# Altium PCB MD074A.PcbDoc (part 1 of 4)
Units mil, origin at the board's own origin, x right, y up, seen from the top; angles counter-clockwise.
Board outline 3224.41 x 4078.74 mil, 4 copper layers (Top Layer, Signal Layer 1, Signal Layer 2, Bottom Layer), stack 61.2 mil thick; 217 components, 121 nets, 624 pads, 901 vias.
Unrouted connection lines stored in the file: 116.
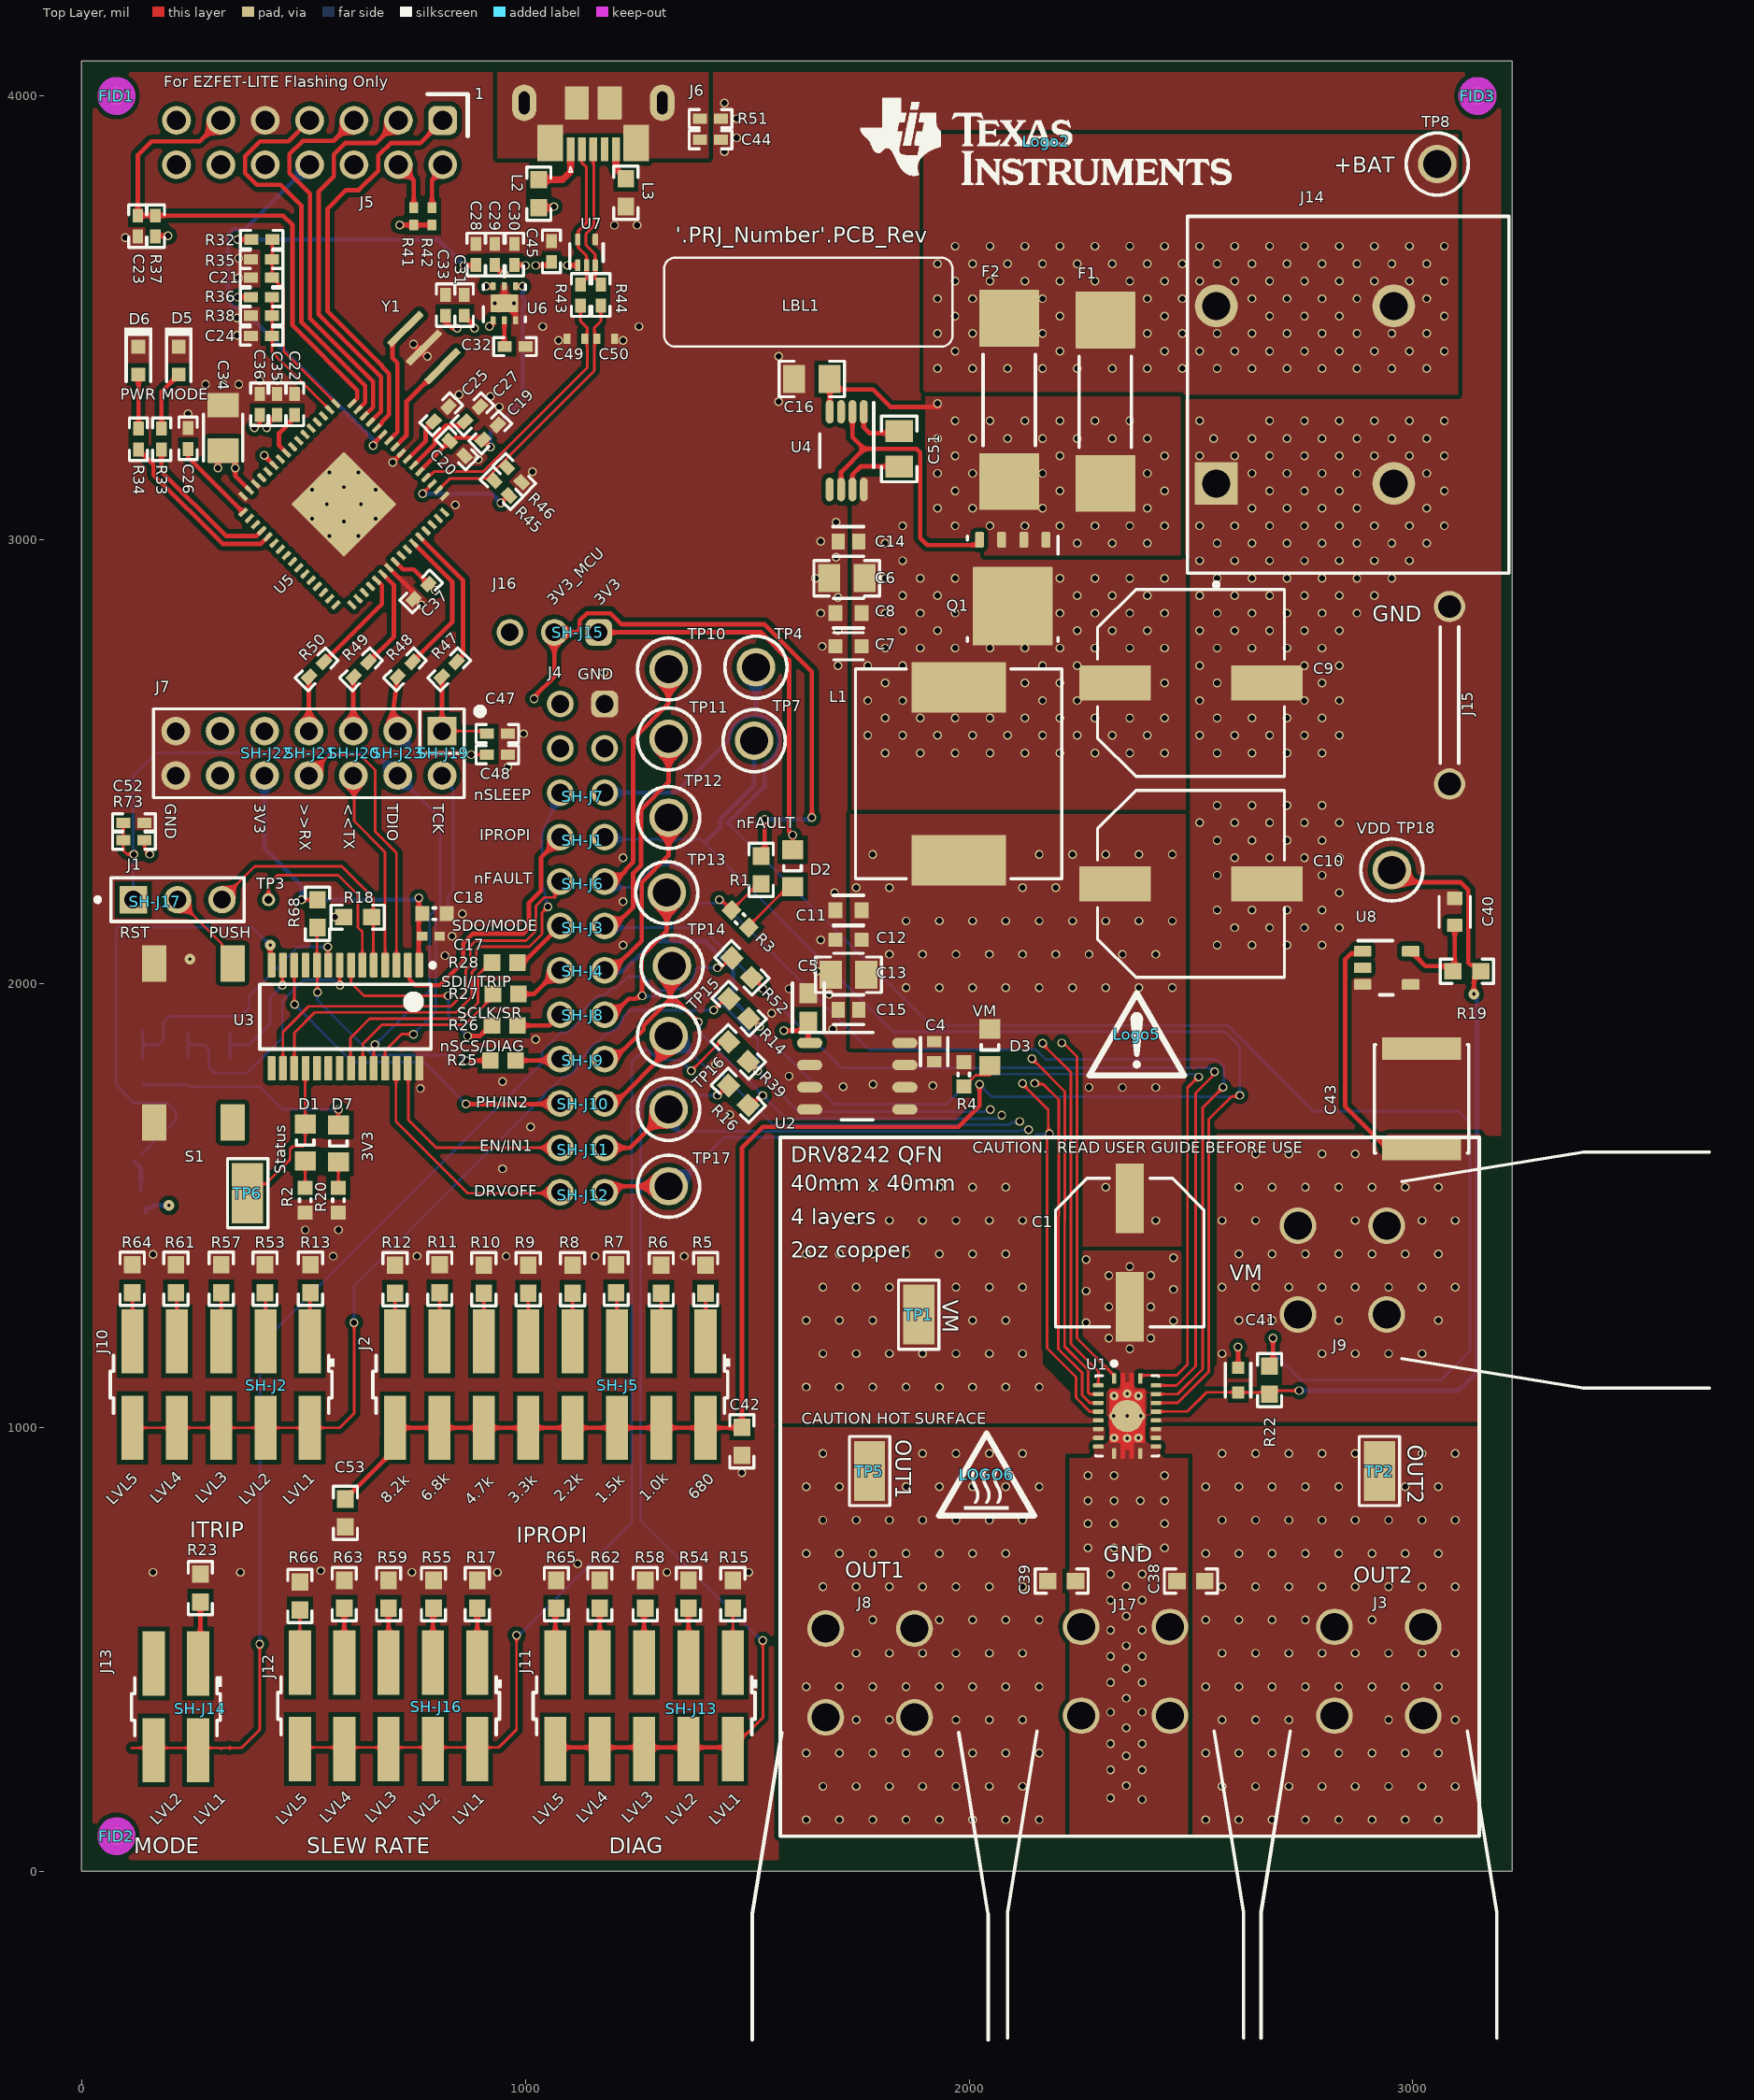
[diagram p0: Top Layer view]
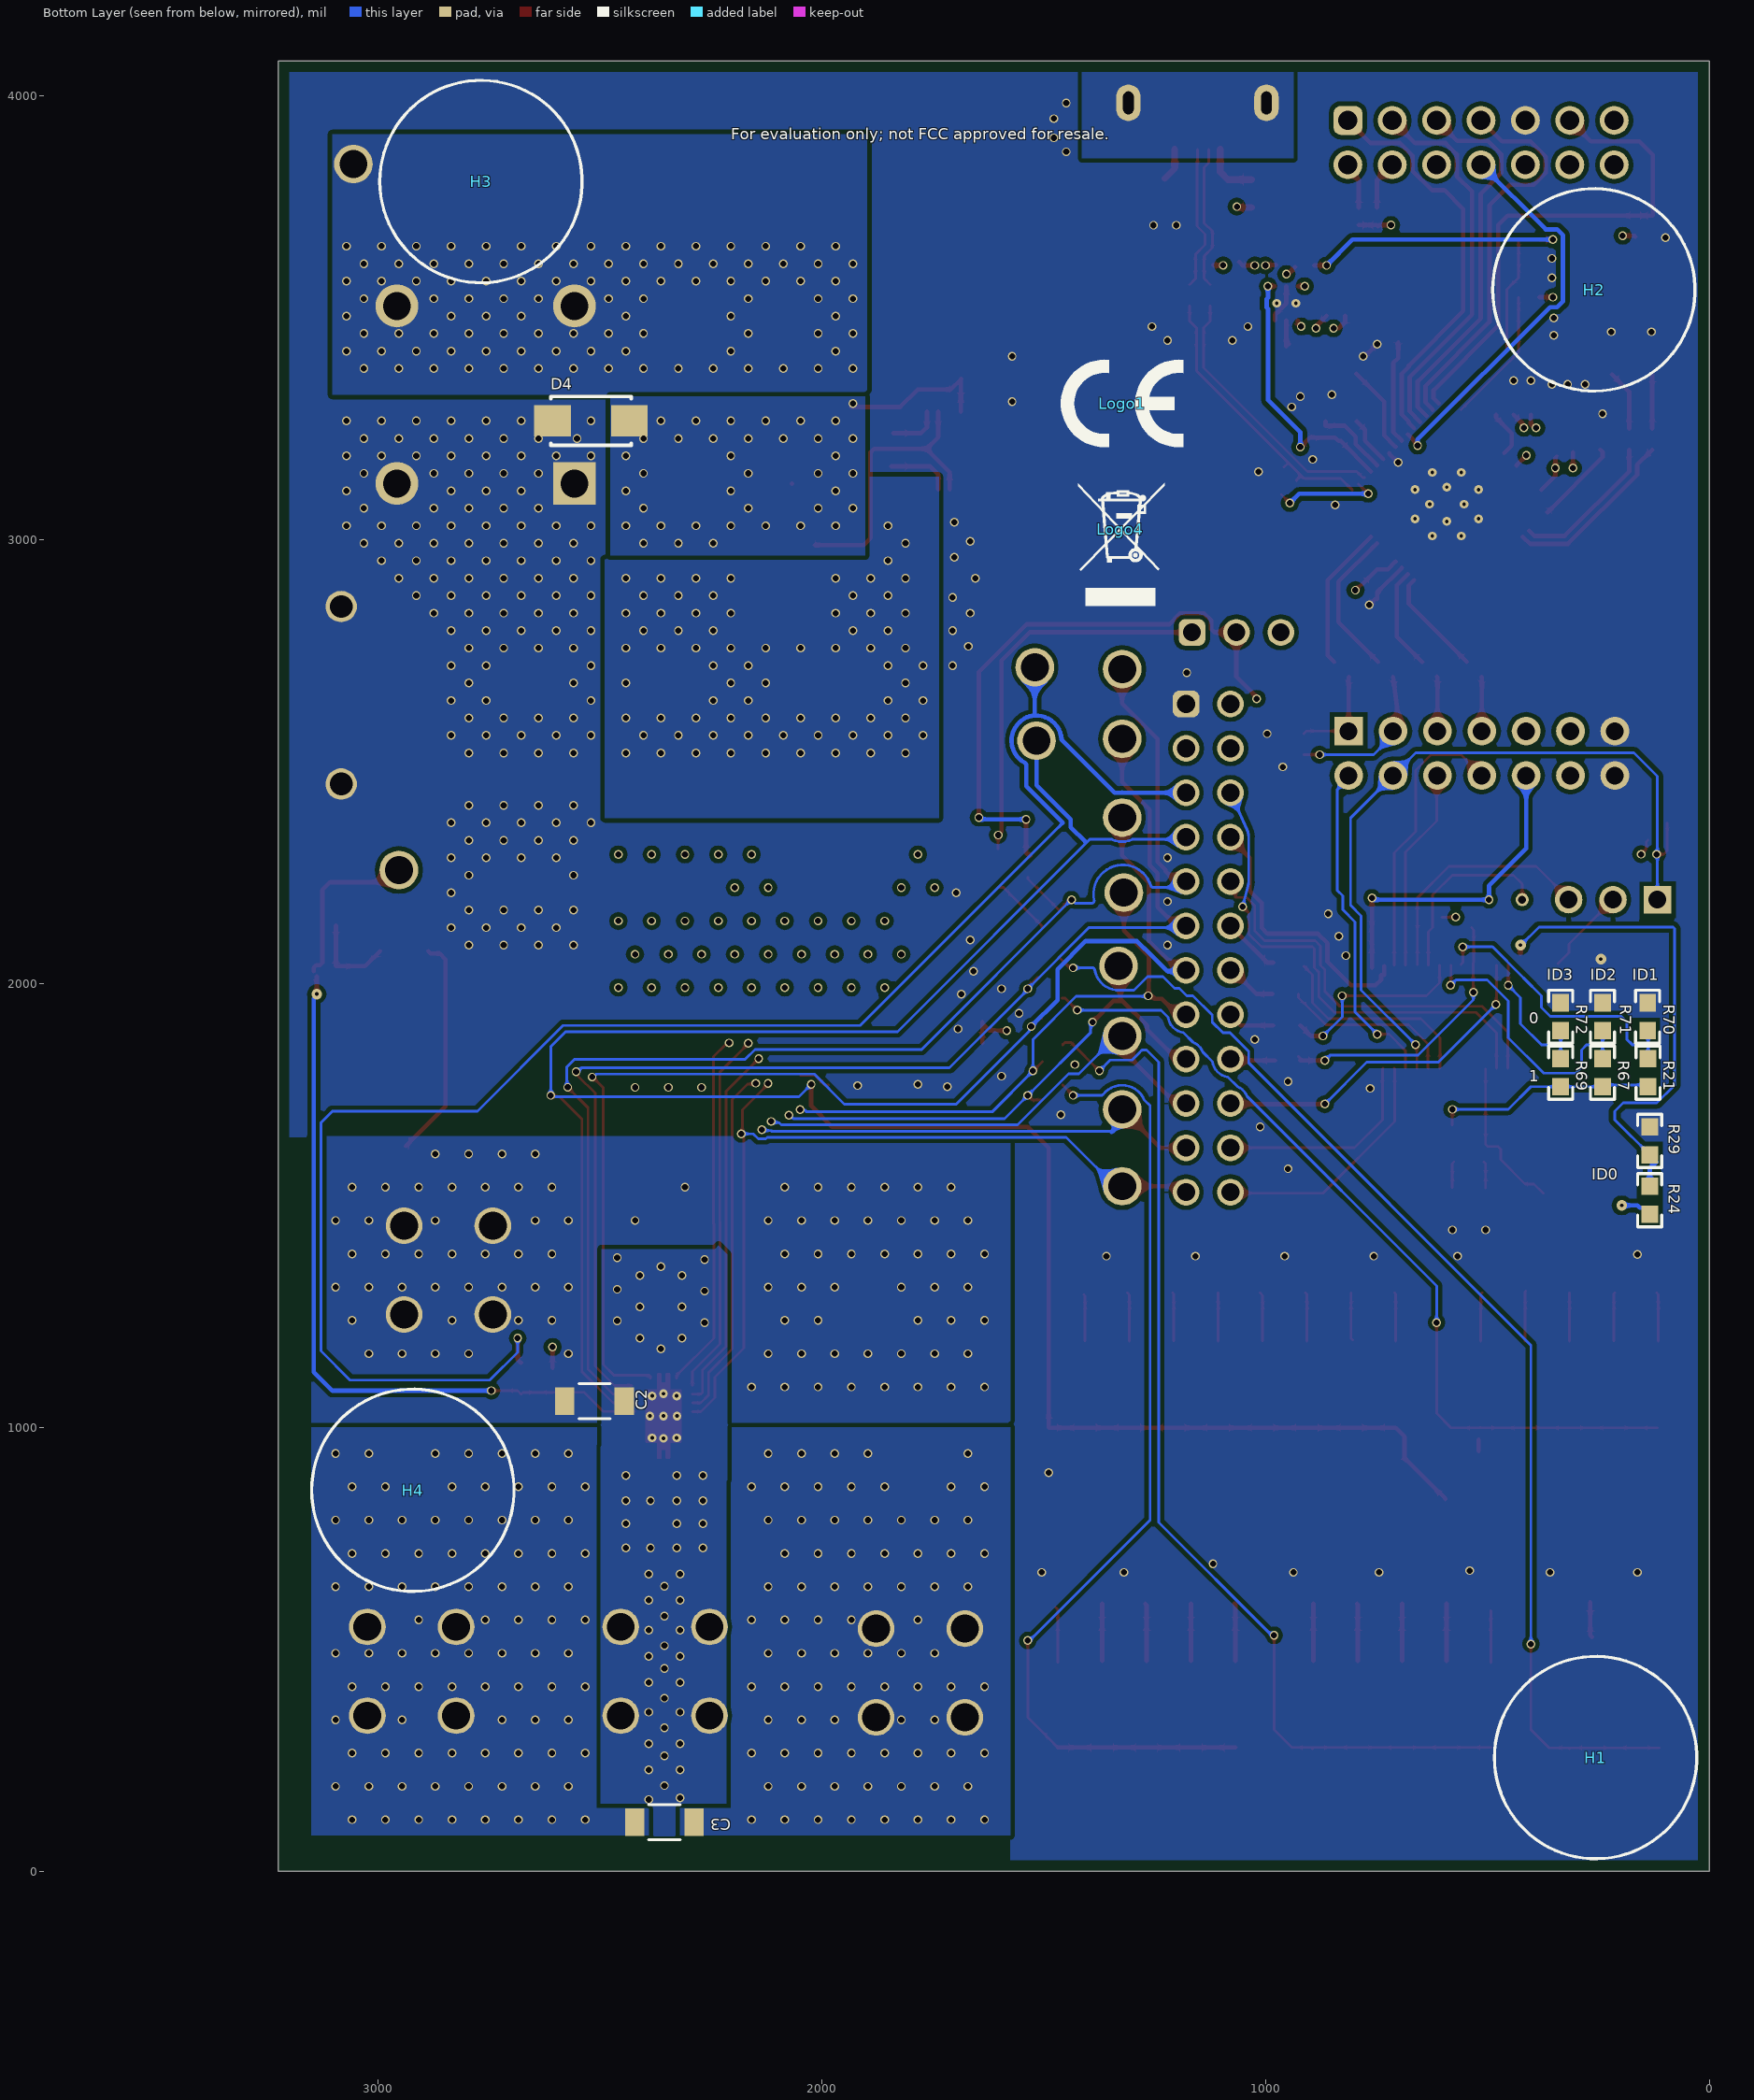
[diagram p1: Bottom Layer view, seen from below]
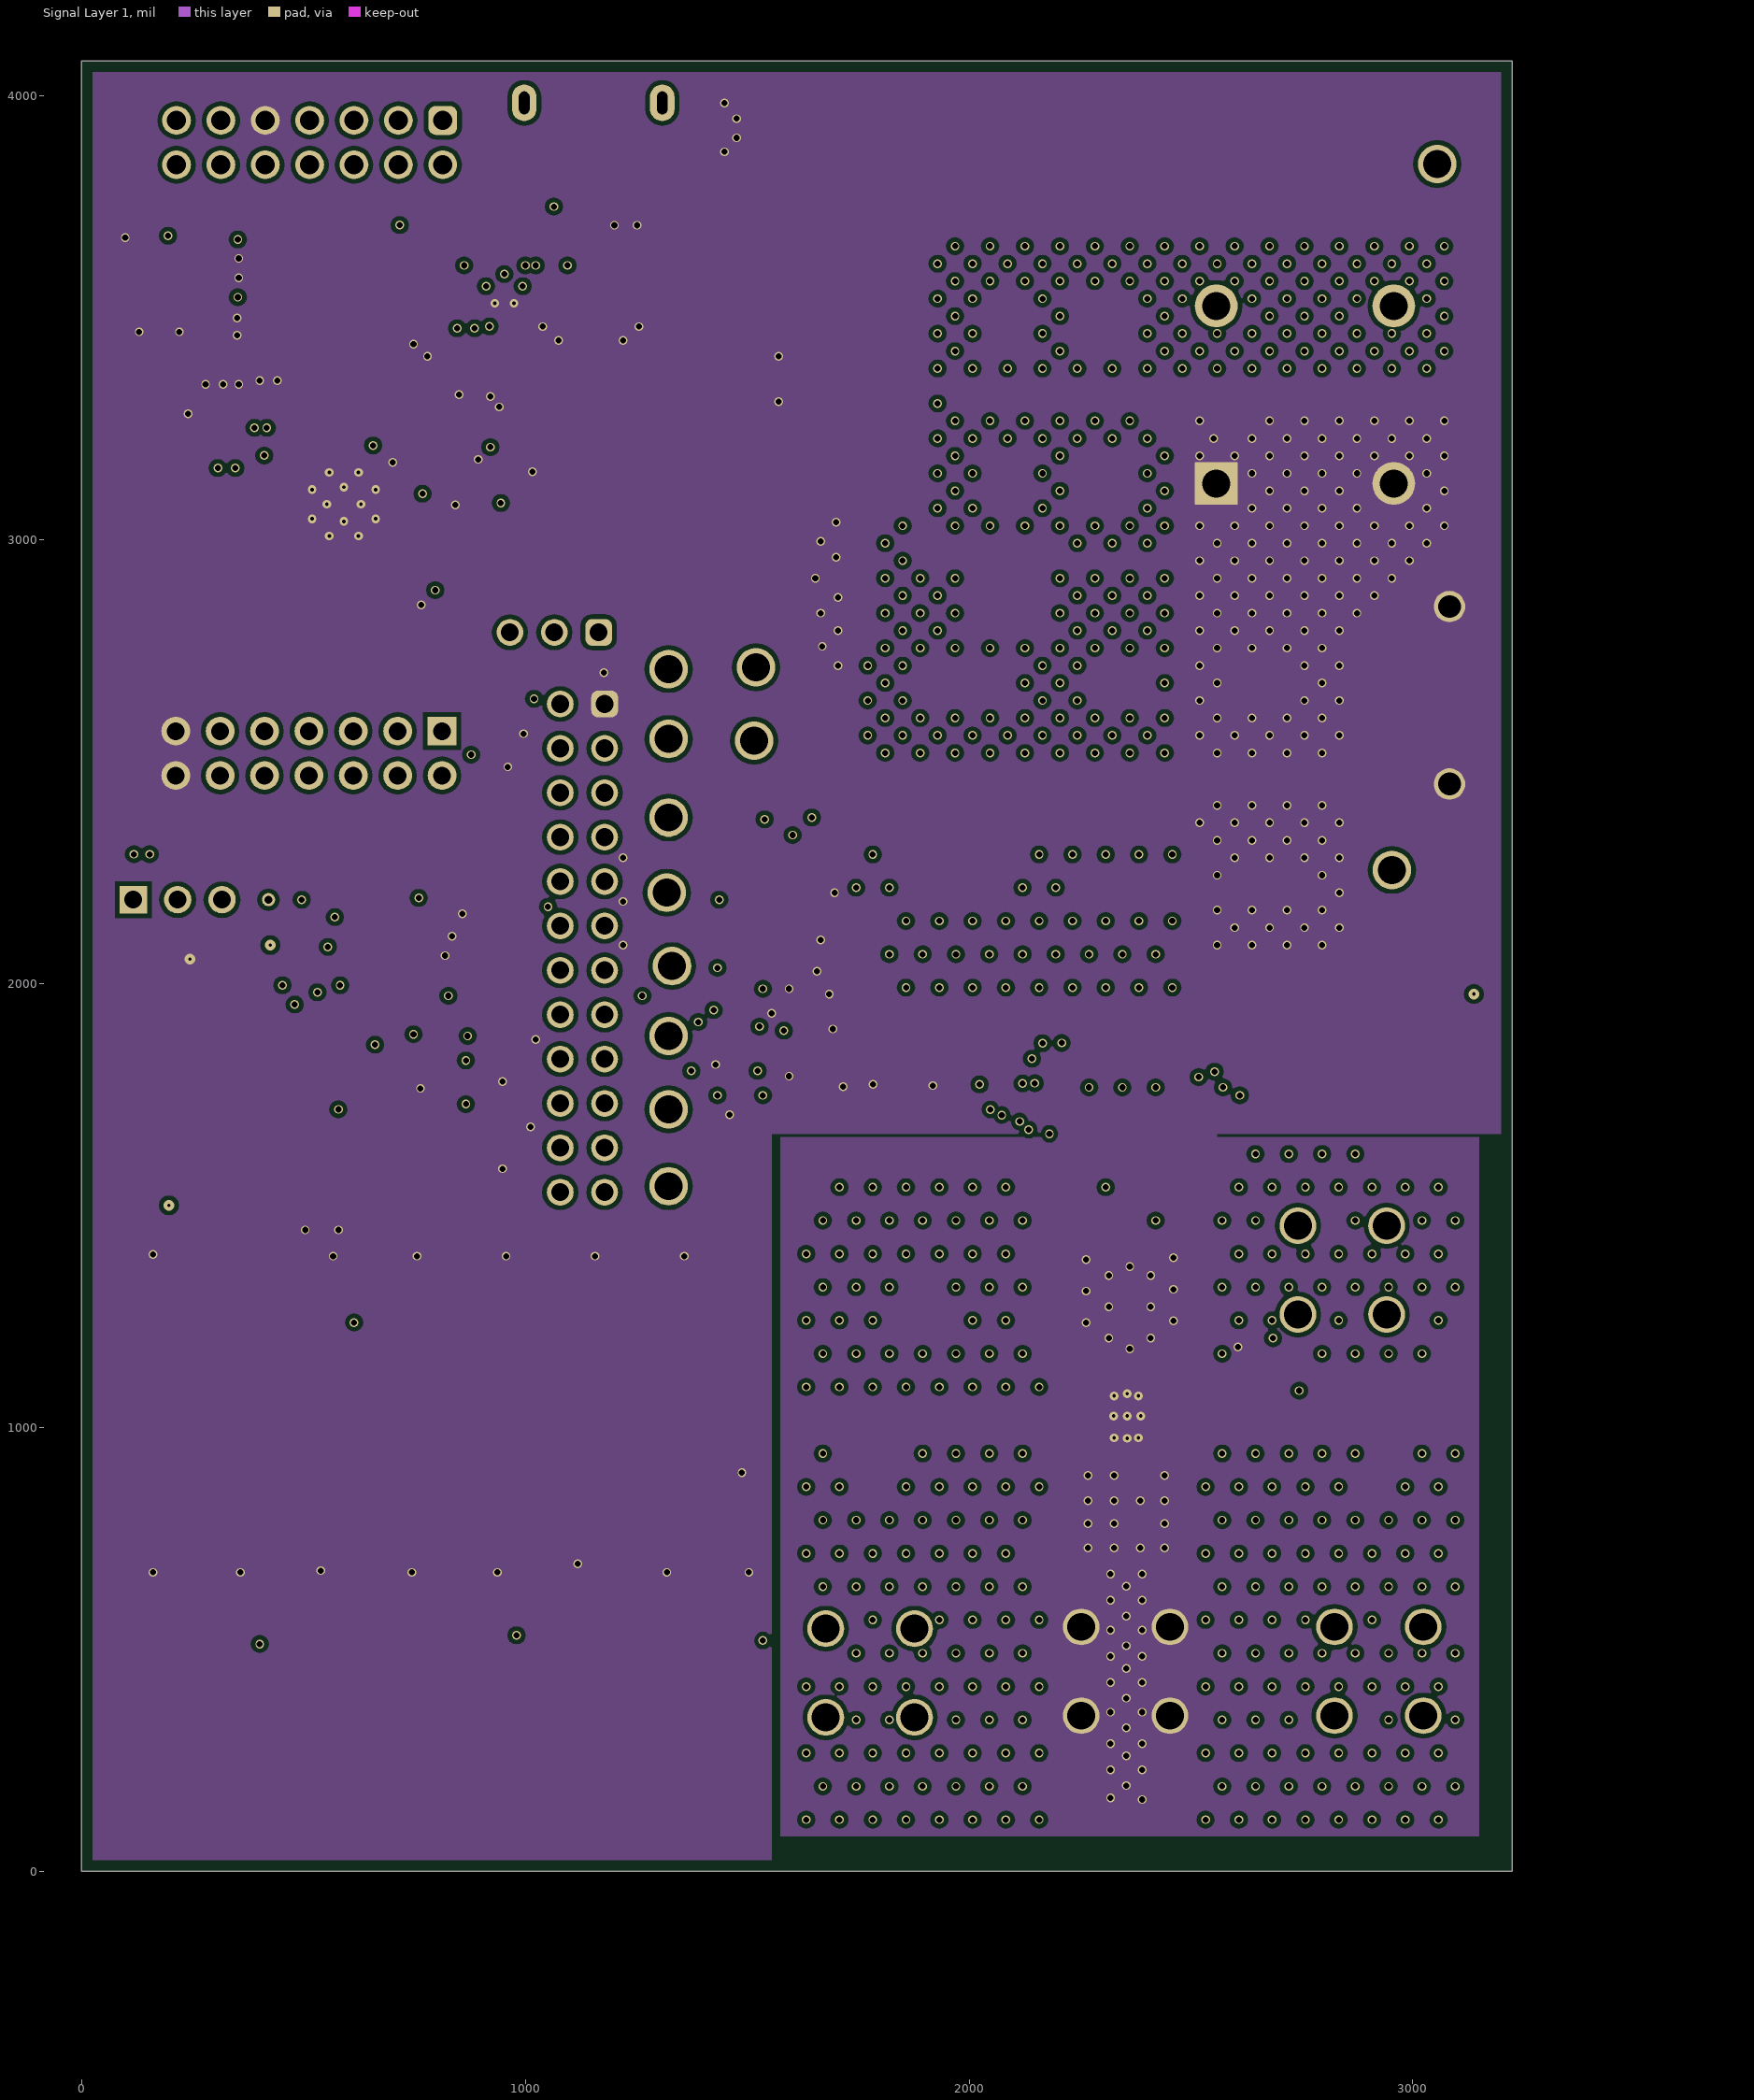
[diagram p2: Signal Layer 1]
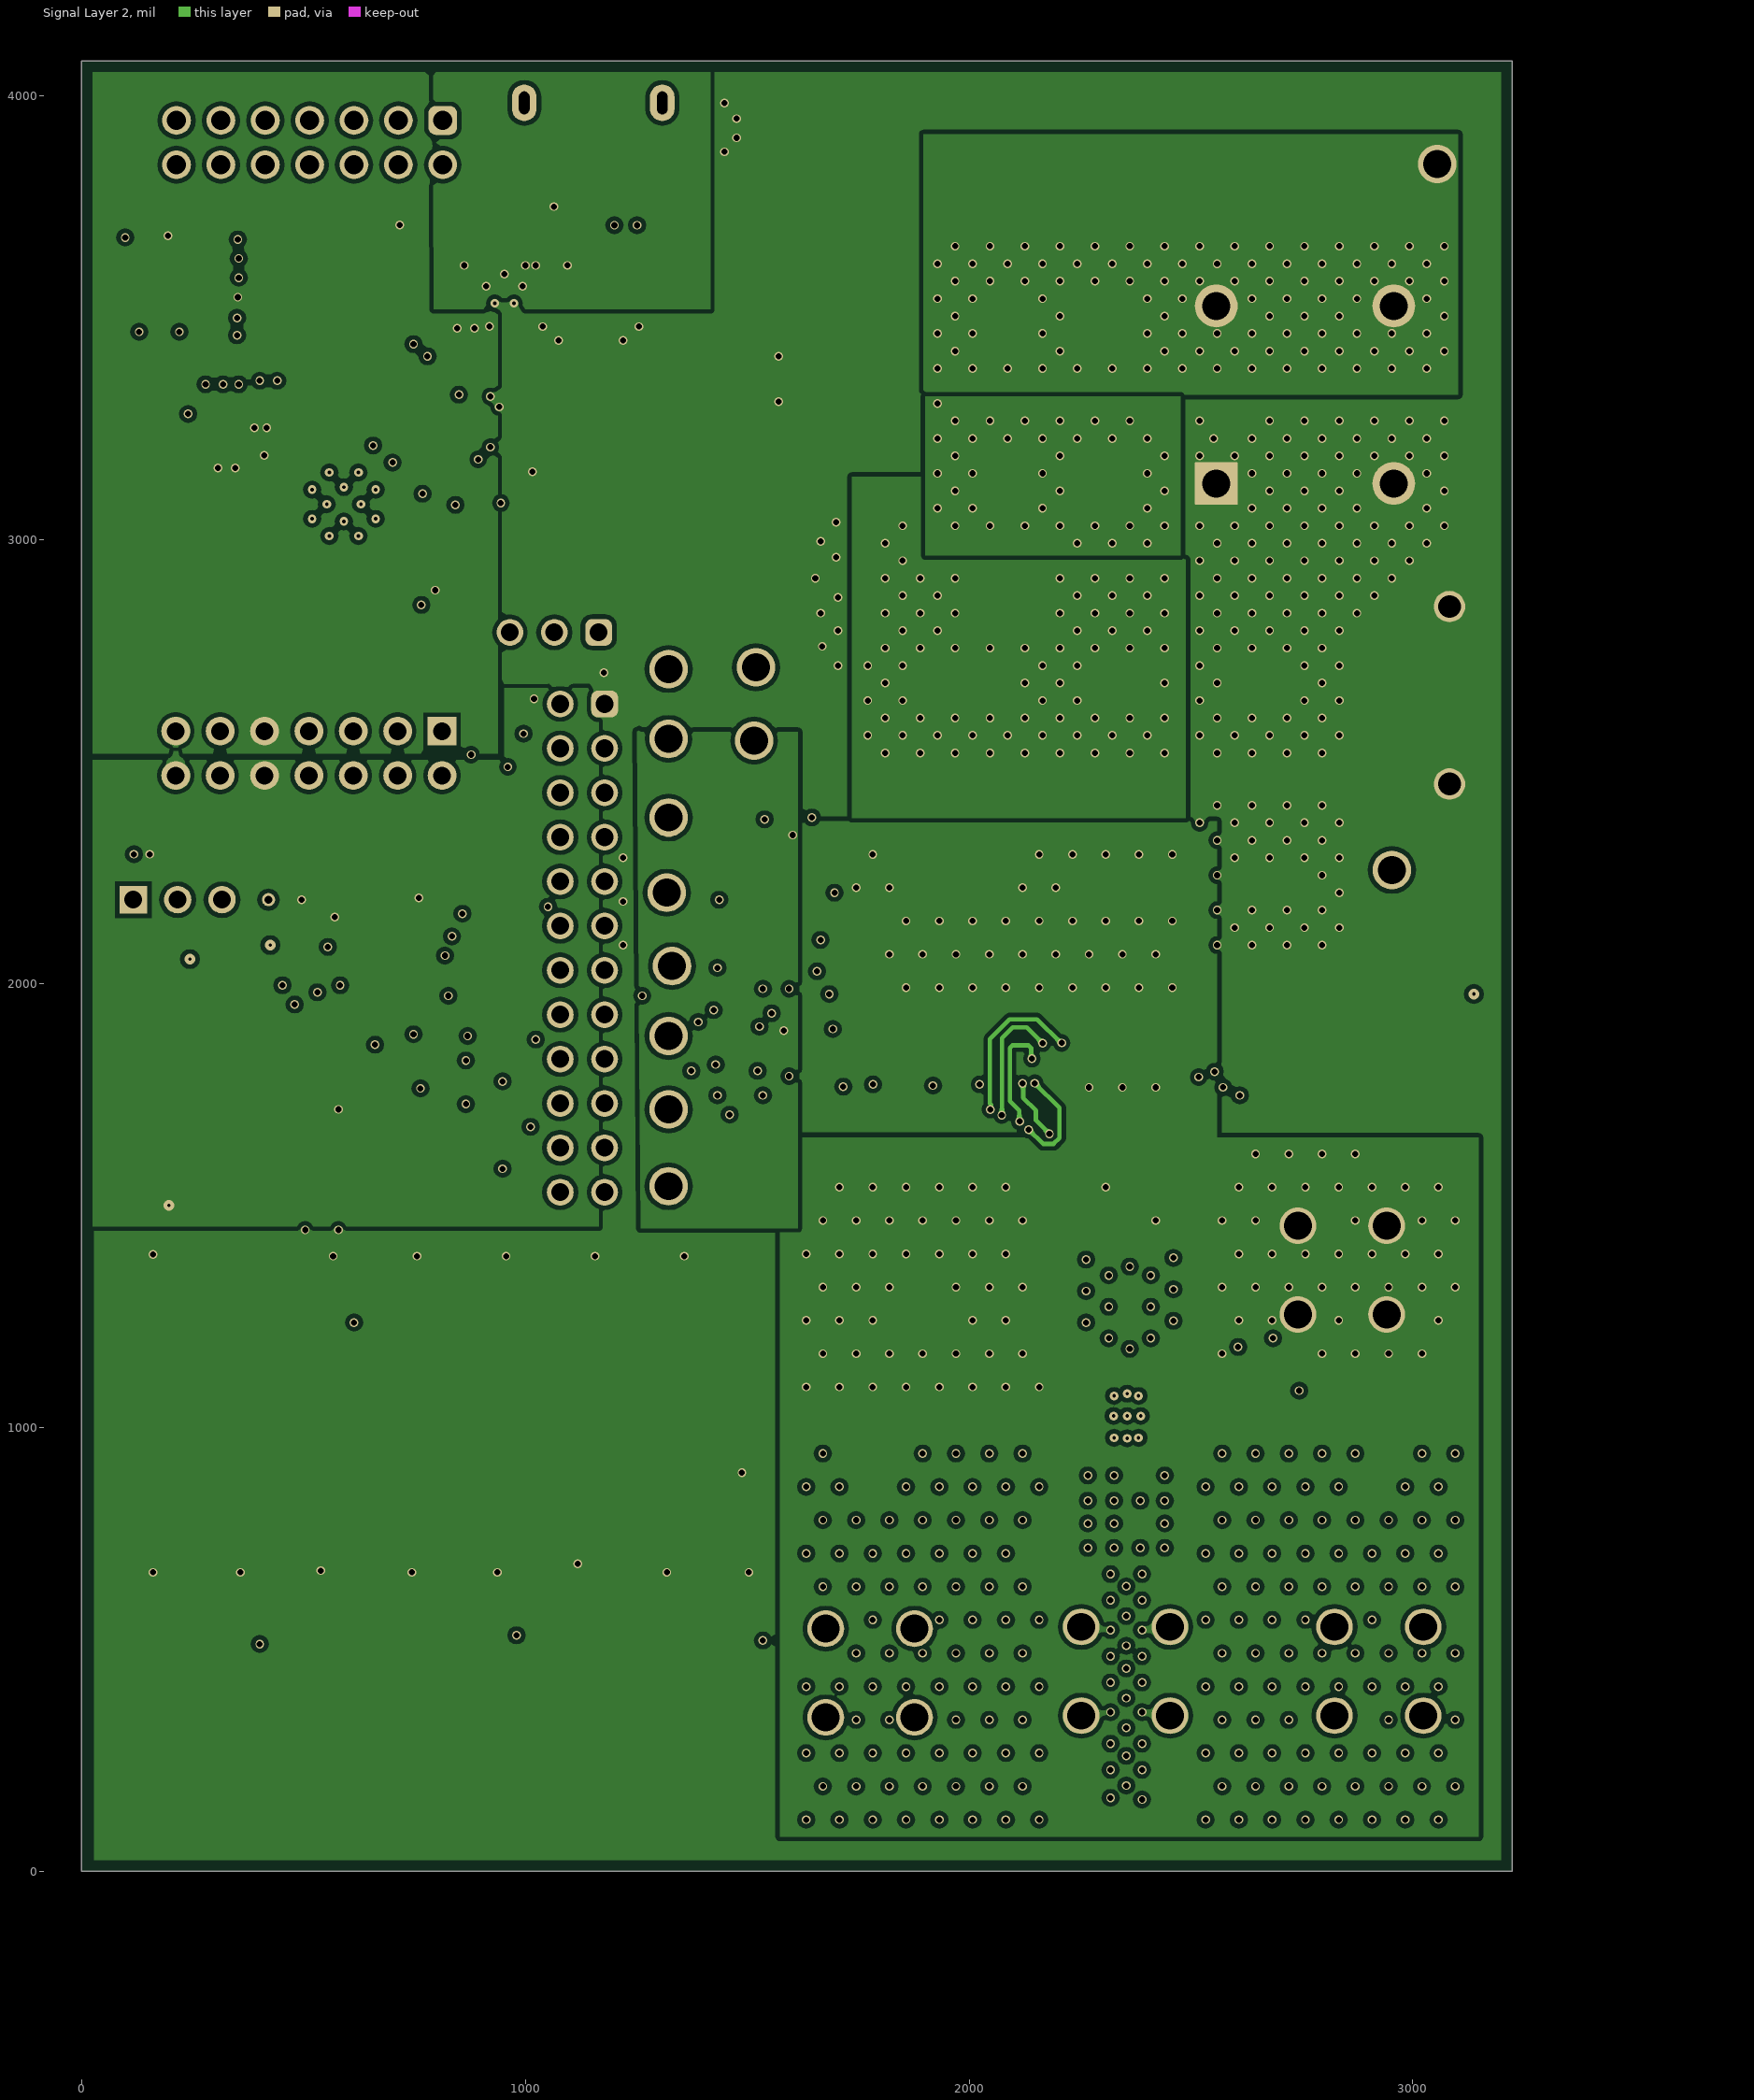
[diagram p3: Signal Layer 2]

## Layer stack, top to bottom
Top Solder: solder mask 0.4, Solder Resist, Dk 3.5
Top Layer: signal copper 2.8
Dielectric 1: prepreg 11.4, FR4 370, Dk 4.2
Signal Layer 1: signal copper 1.4
Dielectric 2: core 30, FR4 370, Dk 4.2
Signal Layer 2: signal copper 1.4
Dielectric 3: prepreg 11.4, FR4 370, Dk 4.2
Bottom Layer: signal copper 2.8
Bottom Solder: solder mask 0.4, Solder Resist, Dk 3.5

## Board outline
0,0 3224.41,0 3224.41,4078.74 0,4078.74

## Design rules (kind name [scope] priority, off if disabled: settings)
AcuteAngle [All] p1: minimum=4.50000000000000E+0001 checktracksonly=FALSE
AssemblyTestPointUsage [All] p1: valid=2
BoardOutlineClearance BoardOutlineClearance_MountingHoles [OnCopper and InComponentClass('Mounting Holes')] p1: gap=39.37 ignorepadtopadclearanceinfootprint=FALSE
BoardOutlineClearance BoardOutlineClearance_Poly [OnCopper and IsPoly] p2: gap=25 ignorepadtopadclearanceinfootprint=FALSE
BoardOutlineClearance [OnCopper and Not InComponentClass('Logo') and not InComponentClass('FiducialMark') and not InRegion(1000,500,4000,800) and not InPoly] p3: gap=75 ignorepadtopadclearanceinfootprint=FALSE
Clearance Clearance_99 [InNamedPolygon('TOP_LAYER_OUT2_P270')] p1: gap=10 ignorepadtopadclearanceinfootprint=TRUE except(0: Arc-Hole Track-Hole SMDPad-Hole THPad-Hole Via-Hole Fill-Hole Poly-Hole Region-Hole Text-Hole)
Clearance Clearance_98 [InNamedPolygon('TOP_LAYER_EZFET_USB_SHIELD_P273')] p2: gap=10 ignorepadtopadclearanceinfootprint=TRUE except(0: Arc-Hole Track-Hole SMDPad-Hole THPad-Hole Via-Hole Fill-Hole Poly-Hole Region-Hole Text-Hole)
Clearance Clearance_97 [InNamedPolygon('TOP_LAYER_P_IN_P276')] p3: gap=10 ignorepadtopadclearanceinfootprint=TRUE except(0: Arc-Hole Track-Hole SMDPad-Hole THPad-Hole Via-Hole Fill-Hole Poly-Hole Region-Hole Text-Hole)
Clearance Clearance_96 [InNamedPolygon('SIGNAL_LAYER_2_NONET_P294')] p4: gap=10 ignorepadtopadclearanceinfootprint=TRUE except(0: Arc-Hole Track-Hole SMDPad-Hole THPad-Hole Via-Hole Fill-Hole Poly-Hole Region-Hole Text-Hole)
Clearance Clearance_95 [InNamedPolygon('TOP_LAYER_GND_P283')] p5: gap=10 ignorepadtopadclearanceinfootprint=TRUE except(0: Arc-Hole Track-Hole SMDPad-Hole THPad-Hole Via-Hole Fill-Hole Poly-Hole Region-Hole Text-Hole)
Clearance Clearance_94 [InNamedPolygon('TOP_LAYER_OUT1_P281')] p6: gap=10 ignorepadtopadclearanceinfootprint=TRUE except(0: Arc-Hole Track-Hole SMDPad-Hole THPad-Hole Via-Hole Fill-Hole Poly-Hole Region-Hole Text-Hole)
Clearance Clearance_93 [InNamedPolygon('TOP_LAYER_OUT2_P269')] p7: gap=10 ignorepadtopadclearanceinfootprint=TRUE except(0: Arc-Hole Track-Hole SMDPad-Hole THPad-Hole Via-Hole Fill-Hole Poly-Hole Region-Hole Text-Hole)
Clearance Clearance_92 [InNamedPolygon('TOP_LAYER_OUT2_P268')] p8: gap=10 ignorepadtopadclearanceinfootprint=TRUE except(0: Arc-Hole Track-Hole SMDPad-Hole THPad-Hole Via-Hole Fill-Hole Poly-Hole Region-Hole Text-Hole)
Clearance Clearance_91 [InNamedPolygon('SIGNAL_LAYER_2_VM_P256')] p9: gap=10 ignorepadtopadclearanceinfootprint=FALSE
Clearance Clearance_90 [InNamedPolygon('SIGNAL_LAYER_2_VM_P256')] p10: gap=0 ignorepadtopadclearanceinfootprint=FALSE
Clearance "Stitching OUT2" [IsStitchingVia and InNet('OUT2') vs (IsVia and (Not IsStitchingVia)) Or IsPad] p11: gap=5 ignorepadtopadclearanceinfootprint=TRUE
Clearance "Stitching OUT1" [IsStitchingVia and InNet('OUT1') vs (IsVia and (Not IsStitchingVia)) Or IsPad] p12: gap=5 ignorepadtopadclearanceinfootprint=TRUE
Clearance Clearance_89 [InNamedPolygon('TOP_LAYER_OUT1_P125')] p13: gap=10 ignorepadtopadclearanceinfootprint=TRUE except(0: Arc-Hole Track-Hole SMDPad-Hole THPad-Hole Via-Hole Fill-Hole Poly-Hole Region-Hole Text-Hole)
Clearance Clearance_88 [InNamedPolygon('TOP_LAYER_NONET_P-001')] p14: gap=10 ignorepadtopadclearanceinfootprint=TRUE except(0: Arc-Hole Track-Hole SMDPad-Hole THPad-Hole Via-Hole Fill-Hole Poly-Hole Region-Hole Text-Hole)
Clearance Clearance_87 [InNamedPolygon('TOP_LAYER_NONET_P-001')] p15: gap=10 ignorepadtopadclearanceinfootprint=TRUE except(0: Arc-Hole Track-Hole SMDPad-Hole THPad-Hole Via-Hole Fill-Hole Poly-Hole Region-Hole Text-Hole)
Clearance Clearance_86 [InNamedPolygon('TOP_LAYER_GND_P227')] p16: gap=10 ignorepadtopadclearanceinfootprint=TRUE except(0: Arc-Hole Track-Hole SMDPad-Hole THPad-Hole Via-Hole Fill-Hole Poly-Hole Region-Hole Text-Hole)
Clearance Clearance_85 [InNamedPolygon('TOP_LAYER_VM_P229')] p17: gap=10 ignorepadtopadclearanceinfootprint=TRUE except(0: Arc-Hole Track-Hole SMDPad-Hole THPad-Hole Via-Hole Fill-Hole Poly-Hole Region-Hole Text-Hole)
Clearance Clearance_84 [InNamedPolygon('TOP_LAYER_GND_P129')] p18: gap=10 ignorepadtopadclearanceinfootprint=TRUE except(0: Arc-Hole Track-Hole SMDPad-Hole THPad-Hole Via-Hole Fill-Hole Poly-Hole Region-Hole Text-Hole)
Clearance Clearance_83 [InNamedPolygon('TOP_LAYER_OUT1_P221')] p19: gap=3.94 ignorepadtopadclearanceinfootprint=TRUE except(0: Arc-Hole Track-Hole SMDPad-Hole THPad-Hole Via-Hole Fill-Hole Poly-Hole Region-Hole Text-Hole)
Clearance Clearance_82 [InNamedPolygon('TOP_LAYER_OUT1_P125')] p20: gap=10 ignorepadtopadclearanceinfootprint=TRUE except(0: Arc-Hole Track-Hole SMDPad-Hole THPad-Hole Via-Hole Fill-Hole Poly-Hole Region-Hole Text-Hole)
Clearance Clearance_81 [InNamedPolygon('TOP_LAYER_OUT1_P125')] p21: gap=10 ignorepadtopadclearanceinfootprint=TRUE except(0: Arc-Hole Track-Hole SMDPad-Hole THPad-Hole Via-Hole Fill-Hole Poly-Hole Region-Hole Text-Hole)
Clearance Clearance_80 [InNamedPolygon('TOP_LAYER_OUT1_P125')] p22: gap=10 ignorepadtopadclearanceinfootprint=TRUE except(0: Arc-Hole Track-Hole SMDPad-Hole THPad-Hole Via-Hole Fill-Hole Poly-Hole Region-Hole Text-Hole)
Clearance Clearance_79 [InNamedPolygon('TOP_LAYER_OUT1_P221')] p23: gap=10 ignorepadtopadclearanceinfootprint=TRUE except(0: Arc-Hole Track-Hole SMDPad-Hole THPad-Hole Via-Hole Fill-Hole Poly-Hole Region-Hole Text-Hole)
Clearance Clearance_78 [InNamedPolygon('TOP_LAYER_GND_P129')] p24: gap=10 ignorepadtopadclearanceinfootprint=TRUE except(0: Arc-Hole Track-Hole SMDPad-Hole THPad-Hole Via-Hole Fill-Hole Poly-Hole Region-Hole Text-Hole)
Clearance Clearance_77 [InNamedPolygon('TOP_LAYER_OUT2_P119')] p25: gap=10 ignorepadtopadclearanceinfootprint=TRUE except(0: Arc-Hole Track-Hole SMDPad-Hole THPad-Hole Via-Hole Fill-Hole Poly-Hole Region-Hole Text-Hole)
Clearance Clearance_76 [InNamedPolygon('TOP_LAYER_OUT1_P125')] p26: gap=10 ignorepadtopadclearanceinfootprint=TRUE except(0: Arc-Hole Track-Hole SMDPad-Hole THPad-Hole Via-Hole Fill-Hole Poly-Hole Region-Hole Text-Hole)
Clearance Clearance_75 [InNamedPolygon('TOP_LAYER_VM_P085')] p27: gap=10 ignorepadtopadclearanceinfootprint=TRUE except(0: Arc-Hole Track-Hole SMDPad-Hole THPad-Hole Via-Hole Fill-Hole Poly-Hole Region-Hole Text-Hole)
Clearance Clearance_74 [InNamedPolygon('TOP_LAYER_GND_P121')] p28: gap=10 ignorepadtopadclearanceinfootprint=TRUE except(0: Arc-Hole Track-Hole SMDPad-Hole THPad-Hole Via-Hole Fill-Hole Poly-Hole Region-Hole Text-Hole)
Clearance Clearance_73 [InNamedPolygon('TOP_LAYER_OUT2_P119') Or  InNamedPolygon('TOP_LAYER_OUT1_P125')] p29: gap=1.97 ignorepadtopadclearanceinfootprint=TRUE except(0: Arc-Hole Track-Hole SMDPad-Hole THPad-Hole Via-Hole Fill-Hole Poly-Hole Region-Hole Text-Hole)
Clearance Clearance_72 [InNamedPolygon('TOP_LAYER_OUT1_P125') Or  InNamedPolygon('TOP_LAYER_OUT2_P119')] p30: gap=3.94 ignorepadtopadclearanceinfootprint=TRUE except(0: Arc-Hole Track-Hole SMDPad-Hole THPad-Hole Via-Hole Fill-Hole Poly-Hole Region-Hole Text-Hole)
Clearance Clearance_71 [InNamedPolygon('TOP_LAYER_OUT1_P125')] p31: gap=10 ignorepadtopadclearanceinfootprint=TRUE except(0: Arc-Hole Track-Hole SMDPad-Hole THPad-Hole Via-Hole Fill-Hole Poly-Hole Region-Hole Text-Hole)
Clearance Clearance_70 [InNamedPolygon('TOP_LAYER_OUT2_P119')] p32: gap=10 ignorepadtopadclearanceinfootprint=TRUE except(0: Arc-Hole Track-Hole SMDPad-Hole THPad-Hole Via-Hole Fill-Hole Poly-Hole Region-Hole Text-Hole)
Clearance Clearance_69 [InNamedPolygon('TOP_LAYER_OUT1_P125')] p33: gap=3.94 ignorepadtopadclearanceinfootprint=TRUE except(0: Arc-Hole Track-Hole SMDPad-Hole THPad-Hole Via-Hole Fill-Hole Poly-Hole Region-Hole Text-Hole)
Clearance Clearance_68 [InNamedPolygon('TOP_LAYER_OUT2_P119')] p34: gap=3.94 ignorepadtopadclearanceinfootprint=TRUE except(0: Arc-Hole Track-Hole SMDPad-Hole THPad-Hole Via-Hole Fill-Hole Poly-Hole Region-Hole Text-Hole)
Clearance Clearance_67 [InNamedPolygon('TOP_LAYER_VM_P085')] p35: gap=3.94 ignorepadtopadclearanceinfootprint=TRUE except(0: Arc-Hole Track-Hole SMDPad-Hole THPad-Hole Via-Hole Fill-Hole Poly-Hole Region-Hole Text-Hole)
Clearance Clearance_66 [InNamedPolygon('BOTTOM_LAYER_P_IN_P174')] p36: gap=10 ignorepadtopadclearanceinfootprint=TRUE except(0: Arc-Hole Track-Hole SMDPad-Hole THPad-Hole Via-Hole Fill-Hole Poly-Hole Region-Hole Text-Hole)
Clearance Clearance_65 [InNamedPolygon('BOTTOM_LAYER_NETF1_2_P203')] p37: gap=10 ignorepadtopadclearanceinfootprint=TRUE except(0: Arc-Hole Track-Hole SMDPad-Hole THPad-Hole Via-Hole Fill-Hole Poly-Hole Region-Hole Text-Hole)
Clearance Clearance_64 [InNamedPolygon('BOTTOM_LAYER_VBAT_P080')] p38: gap=10 ignorepadtopadclearanceinfootprint=TRUE except(0: Arc-Hole Track-Hole SMDPad-Hole THPad-Hole Via-Hole Fill-Hole Poly-Hole Region-Hole Text-Hole)
Clearance Clearance_63 [InNamedPolygon('TOP_LAYER_VM_P167')] p39: gap=10 ignorepadtopadclearanceinfootprint=TRUE except(0: Arc-Hole Track-Hole SMDPad-Hole THPad-Hole Via-Hole Fill-Hole Poly-Hole Region-Hole Text-Hole)
Clearance Clearance_62 [InNamedPolygon('TOP_LAYER_VM_P167')] p40: gap=10 ignorepadtopadclearanceinfootprint=TRUE except(0: Arc-Hole Track-Hole SMDPad-Hole THPad-Hole Via-Hole Fill-Hole Poly-Hole Region-Hole Text-Hole)
Clearance Clearance_61 [InNamedPolygon('TOP_LAYER_VM_P171')] p41: gap=10 ignorepadtopadclearanceinfootprint=TRUE except(0: Arc-Hole Track-Hole SMDPad-Hole THPad-Hole Via-Hole Fill-Hole Poly-Hole Region-Hole Text-Hole)
Clearance Clearance_60 [InNamedPolygon('SIGNAL_LAYER_2_NETF1_2_P196')] p42: gap=10 ignorepadtopadclearanceinfootprint=TRUE except(0: Arc-Hole Track-Hole SMDPad-Hole THPad-Hole Via-Hole Fill-Hole Poly-Hole Region-Hole Text-Hole)
Clearance Clearance_59 [InNamedPolygon('SIGNAL_LAYER_2_VBAT_P197')] p43: gap=10 ignorepadtopadclearanceinfootprint=TRUE except(0: Arc-Hole Track-Hole SMDPad-Hole THPad-Hole Via-Hole Fill-Hole Poly-Hole Region-Hole Text-Hole)
Clearance Clearance_58 [InNamedPolygon('SIGNAL_LAYER_2_P_IN_P198')] p44: gap=10 ignorepadtopadclearanceinfootprint=TRUE except(0: Arc-Hole Track-Hole SMDPad-Hole THPad-Hole Via-Hole Fill-Hole Poly-Hole Region-Hole Text-Hole)
Clearance Clearance_57 [InNamedPolygon('SIGNAL_LAYER_2_3V3_P194')] p45: gap=10 ignorepadtopadclearanceinfootprint=TRUE except(0: Arc-Hole Track-Hole SMDPad-Hole THPad-Hole Via-Hole Fill-Hole Poly-Hole Region-Hole Text-Hole)
Clearance Clearance_56 [InNamedPolygon('TOP_LAYER_NETF1_2_P201')] p46: gap=10 ignorepadtopadclearanceinfootprint=TRUE except(0: Arc-Hole Track-Hole SMDPad-Hole THPad-Hole Via-Hole Fill-Hole Poly-Hole Region-Hole Text-Hole)
Clearance Clearance_55 [InNamedPolygon('TOP_LAYER_VBAT_P207')] p47: gap=10 ignorepadtopadclearanceinfootprint=TRUE except(0: Arc-Hole Track-Hole SMDPad-Hole THPad-Hole Via-Hole Fill-Hole Poly-Hole Region-Hole Text-Hole)
Clearance Clearance_54 [InNamedPolygon('TOP_LAYER_P_IN_P223')] p48: gap=10 ignorepadtopadclearanceinfootprint=TRUE except(0: Arc-Hole Track-Hole SMDPad-Hole THPad-Hole Via-Hole Fill-Hole Poly-Hole Region-Hole Text-Hole)
Clearance Clearance_53 [InNamedPolygon('TOP_LAYER_GND_P129')] p49: gap=10 ignorepadtopadclearanceinfootprint=TRUE except(0: Arc-Hole Track-Hole SMDPad-Hole THPad-Hole Via-Hole Fill-Hole Poly-Hole Region-Hole Text-Hole)
Clearance Clearance_52 [InNamedPolygon('SIGNAL_LAYER_2_VM_P177') Or  InNamedPolygon('SIGNAL_LAYER_2_VM_P179') Or  InNamedPolygon('SIGNAL_LAYER_2_VM_P160') Or  InNamedPolygon('SIGNAL_LAYER_2_VM_P175') Or  InNamedPolygon('SIGNAL_LAYER_2_VM_P181')] p50: gap=10 ignorepadtopadclearanceinfootprint=TRUE except(0: Arc-Hole Track-Hole SMDPad-Hole THPad-Hole Via-Hole Fill-Hole Poly-Hole Region-Hole Text-Hole)
Clearance Clearance_51 [InNamedPolygon('SIGNAL_LAYER_2_EZFET_VBUS_P136')] p51: gap=10 ignorepadtopadclearanceinfootprint=TRUE except(0: Arc-Hole Track-Hole SMDPad-Hole THPad-Hole Via-Hole Fill-Hole Poly-Hole Region-Hole Text-Hole)
Clearance Clearance_50 [InNamedPolygon('SIGNAL_LAYER_2_EZFET_VCC_P132')] p52: gap=10 ignorepadtopadclearanceinfootprint=TRUE except(0: Arc-Hole Track-Hole SMDPad-Hole THPad-Hole Via-Hole Fill-Hole Poly-Hole Region-Hole Text-Hole)
Clearance Clearance_49 [InNamedPolygon('SIGNAL_LAYER_2_3V3_MCU_P192')] p53: gap=10 ignorepadtopadclearanceinfootprint=TRUE except(0: Arc-Hole Track-Hole SMDPad-Hole THPad-Hole Via-Hole Fill-Hole Poly-Hole Region-Hole Text-Hole)
Clearance Clearance_48 [InNamedPolygon('SIGNAL_LAYER_1_GND_P190')] p54: gap=10 ignorepadtopadclearanceinfootprint=TRUE except(0: Arc-Hole Track-Hole SMDPad-Hole THPad-Hole Via-Hole Fill-Hole Poly-Hole Region-Hole Text-Hole)
Clearance Clearance_47 [InNamedPolygon('SIGNAL_LAYER_1_GND_P184')] p55: gap=10 ignorepadtopadclearanceinfootprint=TRUE except(0: Arc-Hole Track-Hole SMDPad-Hole THPad-Hole Via-Hole Fill-Hole Poly-Hole Region-Hole Text-Hole)
Clearance Clearance_46 [InNamedPolygon('BOTTOM_LAYER_GND_P231')] p56: gap=10 ignorepadtopadclearanceinfootprint=TRUE except(0: Arc-Hole Track-Hole SMDPad-Hole THPad-Hole Via-Hole Fill-Hole Poly-Hole Region-Hole Text-Hole)
Clearance Clearance_45 [InNamedPolygon('BOTTOM_LAYER_GND_P231')] p57: gap=10 ignorepadtopadclearanceinfootprint=TRUE except(0: Arc-Hole Track-Hole SMDPad-Hole THPad-Hole Via-Hole Fill-Hole Poly-Hole Region-Hole Text-Hole)
Clearance Clearance_44 [InNamedPolygon('BOTTOM_LAYER_OUT2_P163')] p58: gap=10 ignorepadtopadclearanceinfootprint=TRUE except(0: Arc-Hole Track-Hole SMDPad-Hole THPad-Hole Via-Hole Fill-Hole Poly-Hole Region-Hole Text-Hole)
Clearance Clearance_43 [InNamedPolygon('BOTTOM_LAYER_VM_P166')] p59: gap=10 ignorepadtopadclearanceinfootprint=TRUE except(0: Arc-Hole Track-Hole SMDPad-Hole THPad-Hole Via-Hole Fill-Hole Poly-Hole Region-Hole Text-Hole)
Clearance Clearance_42 [InNamedPolygon('BOTTOM_LAYER_VM_P219')] p60: gap=10 ignorepadtopadclearanceinfootprint=TRUE except(0: Arc-Hole Track-Hole SMDPad-Hole THPad-Hole Via-Hole Fill-Hole Poly-Hole Region-Hole Text-Hole)
Clearance Clearance_41 [InNamedPolygon('BOTTOM_LAYER_OUT1_P164')] p61: gap=10 ignorepadtopadclearanceinfootprint=TRUE except(0: Arc-Hole Track-Hole SMDPad-Hole THPad-Hole Via-Hole Fill-Hole Poly-Hole Region-Hole Text-Hole)
Clearance Clearance_40 [InNamedPolygon('BOTTOM_LAYER_GND_P162')] p62: gap=10 ignorepadtopadclearanceinfootprint=TRUE except(0: Arc-Hole Track-Hole SMDPad-Hole THPad-Hole Via-Hole Fill-Hole Poly-Hole Region-Hole Text-Hole)
Clearance Clearance_39 [InNamedPolygon('SIGNAL_LAYER_2_VM_P160')] p63: gap=10 ignorepadtopadclearanceinfootprint=TRUE except(0: Arc-Hole Track-Hole SMDPad-Hole THPad-Hole Via-Hole Fill-Hole Poly-Hole Region-Hole Text-Hole)
Clearance Clearance_38 [InNamedPolygon('SIGNAL_LAYER_2_NONET_P138')] p64: gap=10 ignorepadtopadclearanceinfootprint=TRUE except(0: Arc-Hole Track-Hole SMDPad-Hole THPad-Hole Via-Hole Fill-Hole Poly-Hole Region-Hole Text-Hole)
Clearance Clearance_37 [InNamedPolygon('SIGNAL_LAYER_1_VM_P146')] p65: gap=10 ignorepadtopadclearanceinfootprint=TRUE except(0: Arc-Hole Track-Hole SMDPad-Hole THPad-Hole Via-Hole Fill-Hole Poly-Hole Region-Hole Text-Hole)
Clearance Clearance_36 [InNamedPolygon('SIGNAL_LAYER_2_GND_P156')] p66: gap=10 ignorepadtopadclearanceinfootprint=TRUE except(0: Arc-Hole Track-Hole SMDPad-Hole THPad-Hole Via-Hole Fill-Hole Poly-Hole Region-Hole Text-Hole)
Clearance Clearance_35 [InNamedPolygon('SIGNAL_LAYER_1_VM_P148') Or  InNamedPolygon('SIGNAL_LAYER_1_VM_P148')] p67: gap=10 ignorepadtopadclearanceinfootprint=TRUE except(0: Arc-Hole Track-Hole SMDPad-Hole THPad-Hole Via-Hole Fill-Hole Poly-Hole Region-Hole Text-Hole)
Clearance Clearance_34 [InNamedPolygon('SIGNAL_LAYER_1_GND_P154')] p68: gap=10 ignorepadtopadclearanceinfootprint=TRUE except(0: Arc-Hole Track-Hole SMDPad-Hole THPad-Hole Via-Hole Fill-Hole Poly-Hole Region-Hole Text-Hole)
Clearance Clearance_33 [InNamedPolygon('SIGNAL_LAYER_2_NONET_P138')] p69: gap=10 ignorepadtopadclearanceinfootprint=TRUE except(0: Arc-Hole Track-Hole SMDPad-Hole THPad-Hole Via-Hole Fill-Hole Poly-Hole Region-Hole Text-Hole)
Clearance Clearance_32 [InNamedPolygon('SIGNAL_LAYER_2_GND_P082')] p70: gap=10 ignorepadtopadclearanceinfootprint=TRUE except(0: Arc-Hole Track-Hole SMDPad-Hole THPad-Hole Via-Hole Fill-Hole Poly-Hole Region-Hole Text-Hole)
Clearance Clearance_31 [InNamedPolygon('TOP_LAYER_GND_P076')] p71: gap=10 ignorepadtopadclearanceinfootprint=TRUE except(0: Arc-Hole Track-Hole SMDPad-Hole THPad-Hole Via-Hole Fill-Hole Poly-Hole Region-Hole Text-Hole)
Clearance Clearance_30 [InNamedPolygon('TOP_LAYER_GND_P087')] p72: gap=10 ignorepadtopadclearanceinfootprint=TRUE except(0: Arc-Hole Track-Hole SMDPad-Hole THPad-Hole Via-Hole Fill-Hole Poly-Hole Region-Hole Text-Hole)
Clearance Clearance_29 [InNamedPolygon('TOP_LAYER_VM_P127') Or  InNamedPolygon('TOP_LAYER_VM_P085')] p73: gap=10 ignorepadtopadclearanceinfootprint=TRUE except(0: Arc-Hole Track-Hole SMDPad-Hole THPad-Hole Via-Hole Fill-Hole Poly-Hole Region-Hole Text-Hole)
Clearance Clearance_28 [InNamedPolygon('TOP_LAYER_GND_P117')] p74: gap=10 ignorepadtopadclearanceinfootprint=TRUE except(0: Arc-Hole Track-Hole SMDPad-Hole THPad-Hole Via-Hole Fill-Hole Poly-Hole Region-Hole Text-Hole)
Clearance Clearance_27 [InNamedPolygon('TOP_LAYER_OUT2_P119') Or  InNamedPolygon('TOP_LAYER_OUT1_P125')] p75: gap=10 ignorepadtopadclearanceinfootprint=TRUE except(0: Arc-Hole Track-Hole SMDPad-Hole THPad-Hole Via-Hole Fill-Hole Poly-Hole Region-Hole Text-Hole)
Clearance Clearance_26 [InNamedPolygon('SIGNAL_LAYER_2_NONET_P113')] p76: gap=10 ignorepadtopadclearanceinfootprint=TRUE except(0: Arc-Hole Track-Hole SMDPad-Hole THPad-Hole Via-Hole Fill-Hole Poly-Hole Region-Hole Text-Hole)
Clearance Clearance_25 [InNamedPolygon('BOTTOM_LAYER_NONET_P115')] p77: gap=10 ignorepadtopadclearanceinfootprint=TRUE except(0: Arc-Hole Track-Hole SMDPad-Hole THPad-Hole Via-Hole Fill-Hole Poly-Hole Region-Hole Text-Hole)
Clearance Clearance_24 [InNamedPolygon('SIGNAL_LAYER_1_NONET_P111')] p78: gap=10 ignorepadtopadclearanceinfootprint=TRUE except(0: Arc-Hole Track-Hole SMDPad-Hole THPad-Hole Via-Hole Fill-Hole Poly-Hole Region-Hole Text-Hole)
Clearance Clearance_23 [InNamedPolygon('TOP_LAYER_NONET_P083')] p79: gap=10 ignorepadtopadclearanceinfootprint=TRUE except(0: Arc-Hole Track-Hole SMDPad-Hole THPad-Hole Via-Hole Fill-Hole Poly-Hole Region-Hole Text-Hole)
Clearance Clearance_22 [InNamedPolygon('TOP_LAYER_NONET_P105')] p80: gap=10 ignorepadtopadclearanceinfootprint=TRUE except(0: Arc-Hole Track-Hole SMDPad-Hole THPad-Hole Via-Hole Fill-Hole Poly-Hole Region-Hole Text-Hole)
Clearance Clearance_21 [InNamedPolygon('TOP_LAYER_OUT2_P107')] p81: gap=10 ignorepadtopadclearanceinfootprint=TRUE except(0: Arc-Hole Track-Hole SMDPad-Hole THPad-Hole Via-Hole Fill-Hole Poly-Hole Region-Hole Text-Hole)
Clearance Clearance_20 [InNamedPolygon('TOP_LAYER_NONET_P101')] p82: gap=10 ignorepadtopadclearanceinfootprint=TRUE except(0: Arc-Hole Track-Hole SMDPad-Hole THPad-Hole Via-Hole Fill-Hole Poly-Hole Region-Hole Text-Hole)
Clearance Clearance_19 [InNamedPolygon('TOP_LAYER_OUT1_P103')] p83: gap=10 ignorepadtopadclearanceinfootprint=TRUE except(0: Arc-Hole Track-Hole SMDPad-Hole THPad-Hole Via-Hole Fill-Hole Poly-Hole Region-Hole Text-Hole)
Clearance Clearance_18 [InNet('OUT1')] p84: gap=10 ignorepadtopadclearanceinfootprint=TRUE except(0: Arc-Hole Track-Hole SMDPad-Hole THPad-Hole Via-Hole Fill-Hole Poly-Hole Region-Hole Text-Hole)
Clearance Clearance_17 [InNamedPolygon('TOP_LAYER_OUT1_P000')] p85: gap=10 ignorepadtopadclearanceinfootprint=TRUE except(0: Arc-Hole Track-Hole SMDPad-Hole THPad-Hole Via-Hole Fill-Hole Poly-Hole Region-Hole Text-Hole)
Clearance Clearance_16 [InNamedPolygon('TOP_LAYER_OUT1_P000') vs InNet('OUT1')] p86: gap=3.94 ignorepadtopadclearanceinfootprint=TRUE except(0: Arc-Hole Track-Hole SMDPad-Hole THPad-Hole Via-Hole Fill-Hole Poly-Hole Region-Hole Text-Hole)
Clearance Clearance_15 [InNamedPolygon('TOP_LAYER_OUT1_P000')] p87: gap=3.94 ignorepadtopadclearanceinfootprint=TRUE except(0: Arc-Hole Track-Hole SMDPad-Hole THPad-Hole Via-Hole Fill-Hole Poly-Hole Region-Hole Text-Hole)
Clearance Clearance_14 [InNamedPolygon('TOP_LAYER_NONET_P093')] p88: gap=3.94 ignorepadtopadclearanceinfootprint=TRUE except(0: Arc-Hole Track-Hole SMDPad-Hole THPad-Hole Via-Hole Fill-Hole Poly-Hole Region-Hole Text-Hole)
Clearance Clearance_13 [InNamedPolygon('TOP_LAYER_NONET_P093')] p89: gap=10 ignorepadtopadclearanceinfootprint=TRUE except(0: Arc-Hole Track-Hole SMDPad-Hole THPad-Hole Via-Hole Fill-Hole Poly-Hole Region-Hole Text-Hole)
Clearance Clearance_12 [InNamedPolygon('TOP_LAYER_OUT2_P099')] p90: gap=10 ignorepadtopadclearanceinfootprint=TRUE except(0: Arc-Hole Track-Hole SMDPad-Hole THPad-Hole Via-Hole Fill-Hole Poly-Hole Region-Hole Text-Hole)
Clearance Clearance_11 [InNamedPolygon('TOP_LAYER_OUT2_P099')] p91: gap=10 ignorepadtopadclearanceinfootprint=TRUE except(0: Arc-Hole Track-Hole SMDPad-Hole THPad-Hole Via-Hole Fill-Hole Poly-Hole Region-Hole Text-Hole)
Clearance Clearance_10 [InNamedPolygon('TOP_LAYER_OUT1_P000')] p92: gap=10 ignorepadtopadclearanceinfootprint=TRUE except(0: Arc-Hole Track-Hole SMDPad-Hole THPad-Hole Via-Hole Fill-Hole Poly-Hole Region-Hole Text-Hole)
Clearance Clearance_9 [InNamedPolygon('TOP_LAYER_OUT1_P000')] p93: gap=10 ignorepadtopadclearanceinfootprint=TRUE except(0: Arc-Hole Track-Hole SMDPad-Hole THPad-Hole Via-Hole Fill-Hole Poly-Hole Region-Hole Text-Hole)
Clearance Clearance_8 [InNamedPolygon('BOTTOM_LAYER_NONET_P079') Or  InNamedPolygon('SIGNAL_LAYER_2_NONET_P078') Or  InNamedPolygon('SIGNAL_LAYER_1_NONET_P077') Or  InNamedPolygon('TOP_LAYER_NONET_P083') Or  InNamedPolygon('BOTTOM_LAYER_NONET_P072') Or  InNamedPolygon('SIGNAL_LAYER_2_NONET_P070') Or  InNamedPolygon('SIGNAL_LAYER_1_NONET_P059') Or  InNamedPolygon('TOP_LAYER_OUT2_P058') Or  InNamedPolygon('BOTTOM_LAYER_NONET_P056') Or  InNamedPolygon('SIGNAL_LAYER_2_NONET_P054') Or  InNamedPolygon('SIGNAL_LAYER_1_NONET_P052') Or  InNamedPolygon('TOP_LAYER_OUT1_P050') Or  InNamedPolygon('BOTTOM_LAYER_VM_P044') Or  InNamedPolygon('SIGNAL_LAYER_2_VM_P042') Or  InNamedPolygon('SIGNAL_LAYER_1_VM_P040') Or  InNamedPolygon('TOP_LAYER_VM_P038') Or  InNamedPolygon('BOTTOM_LAYER_VM_P036') Or  InNamedPolygon('SIGNAL_LAYER_2_VM_P018') Or  InNamedPolygon('SIGNAL_LAYER_1_VM_P016') Or  InNamedPolygon('TOP_LAYER_VM_P002')] p94: gap=10 ignorepadtopadclearanceinfootprint=TRUE except(0: Arc-Hole Track-Hole SMDPad-Hole THPad-Hole Via-Hole Fill-Hole Poly-Hole Region-Hole Text-Hole)
Clearance Clearance_7 [InNamedPolygon('TOP_LAYER_NONET_P089') Or  InNamedPolygon('TOP_LAYER_NONET_P090')] p95: gap=10 ignorepadtopadclearanceinfootprint=TRUE except(0: Arc-Hole Track-Hole SMDPad-Hole THPad-Hole Via-Hole Fill-Hole Poly-Hole Region-Hole Text-Hole)
Clearance Clearance_6 [InNamedPolygon('BOTTOM_LAYER_EZFET_USB_SHIELD_P002') Or  InNamedPolygon('TOP_LAYER_EZFET_USB_SHIELD_P173') Or  InNamedPolygon('SIGNAL_LAYER_2_EZFET_VBUS_P018') Or  InNamedPolygon('SIGNAL_LAYER_2_EZFET_VCC_P016')] p96: gap=10 ignorepadtopadclearanceinfootprint=TRUE except(0: Arc-Hole Track-Hole SMDPad-Hole THPad-Hole Via-Hole Fill-Hole Poly-Hole Region-Hole Text-Hole)
Clearance Clearance_5 [InNamedPolygon('TOP_LAYER_NONET_P072')] p97: gap=10 ignorepadtopadclearanceinfootprint=TRUE except(0: Arc-Hole Track-Hole SMDPad-Hole THPad-Hole Via-Hole Fill-Hole Poly-Hole Region-Hole Text-Hole)
Clearance Clearance_4 [InNamedPolygon('TOP_LAYER_VM_P123') Or  InNamedPolygon('TOP_LAYER_VM_P123') Or  InNamedPolygon('TOP_LAYER_VM_P123')] p98: gap=10 ignorepadtopadclearanceinfootprint=TRUE except(0: Arc-Hole Track-Hole SMDPad-Hole THPad-Hole Via-Hole Fill-Hole Poly-Hole Region-Hole Text-Hole)
Clearance Clearance_3 [InNamedPolygon('TOP_LAYER_VM_P042') Or  InNamedPolygon('TOP_LAYER_VM_P044') Or  InNamedPolygon('TOP_LAYER_OUT2_P040') Or  InNamedPolygon('TOP_LAYER_OUT1_P038')] p99: gap=10 ignorepadtopadclearanceinfootprint=TRUE except(0: Arc-Hole Track-Hole SMDPad-Hole THPad-Hole Via-Hole Fill-Hole Poly-Hole Region-Hole Text-Hole)
Clearance Clearance_2 [InNamedPolygon('TOP_LAYER_OUT2_P040')] p100: gap=10 ignorepadtopadclearanceinfootprint=TRUE except(0: Arc-Hole Track-Hole SMDPad-Hole THPad-Hole Via-Hole Fill-Hole Poly-Hole Region-Hole Text-Hole)
Clearance Clearance_1 [InNamedPolygon('TOP_LAYER_VM_P046')] p101: gap=5.98 ignorepadtopadclearanceinfootprint=TRUE except(0: Arc-Hole Track-Hole SMDPad-Hole THPad-Hole Via-Hole Fill-Hole Poly-Hole Region-Hole Text-Hole)
Clearance Clearance_Keepouts [((IsTrack Or IsArc) And Not InPoly) And IsFree and IsKeepOut vs ((IsTrack Or IsArc) And Not InPoly) And IsFree and IsKeepOut] p102: gap=0 ignorepadtopadclearanceinfootprint=FALSE
Clearance Clearance_Poly [InPolygon] p103: gap=10 ignorepadtopadclearanceinfootprint=TRUE
Clearance Clearance_FiducialMark [IsKeepOut and InComponentClass('FiducialMark') vs IsPad and InComponentClass('FiducialMark')] p104: gap=0 ignorepadtopadclearanceinfootprint=FALSE
Clearance [All] p105: gap=7.87 ignorepadtopadclearanceinfootprint=TRUE
ComponentClearance ComponentClearance_MountingHoles_FiducialMarks [InComponentClass('Mounting Holes') vs InComponentClass('FiducialMark')] p1: gap=50 collisioncheckmode=3 verticalgap=10 showdistances=FALSE
ComponentClearance ComponentClearance_Shunt [InComponentClass('Shunt')] p2: gap=0 collisioncheckmode=3 verticalgap=0 showdistances=FALSE
ComponentClearance ComponentClearance_Logo [InComponentClass('Logo')] p3: gap=50 collisioncheckmode=3 verticalgap=10 showdistances=FALSE
ComponentClearance ComponentClearance_ScrewToNut [(HasFootprint('NY PMS 440 0025 PH')) vs (HasFootprint('Keystone_1902C'))] p4: gap=5 collisioncheckmode=3 verticalgap=10 showdistances=FALSE
ComponentClearance ComponentClearance_MountingHoles [InComponentClass('Mounting Holes')] p5: gap=250 collisioncheckmode=3 verticalgap=100000 showdistances=FALSE
ComponentClearance ComponentClearance_SmallPassives [HasFootprint('0201*') or HasFootprint('0402*') or HasFootprint('0508') or HasFootprint('0603*') or HasFootprint('0612') or HasFootprint('0805*') or HasFootprint('0815*') or HasFootprint('0830*') or HasFootprint('1206*') or HasFootprint('1210*') or HasFootprint('1808*') or HasFootprint('1812*') or HasFootprint('1825*') or HasFootprint('2010*') or HasFootprint('2220*') or HasFootprint('2225*') or HasFootprint('2512*') or HasFootprint('2728*') or HasFootprint('3518*') vs HasFootprint('0201*') or HasFootprint('0402*') or HasFootprint('0508') or HasFootprint('0603*') or HasFootprint('0612') or HasFootprint('0805*') or HasFootprint('0815*') or HasFootprint('0830*') or HasFootprint('1206*') or HasFootprint('1210*') or HasFootprint('1808*') or HasFootprint('1812*') or HasFootprint('1825*') or HasFootprint('2010*') or HasFootprint('2220*') or HasFootprint('2225*') or HasFootprint('2512*') or HasFootprint('2728*') or HasFootprint('3518*')] p6: gap=14.96 collisioncheckmode=3 verticalgap=10 showdistances=FALSE
ComponentClearance ComponentClearance_THtoSMT [IsThruComponent vs IsSMTComponent] p7: gap=40 collisioncheckmode=3 verticalgap=30 showdistances=FALSE
ComponentClearance ComponentClearance_THtoTH [IsThruComponent vs IsThruComponent] p8: gap=30 collisioncheckmode=3 verticalgap=30 showdistances=FALSE
ComponentClearance [All] p9: gap=30 collisioncheckmode=3 verticalgap=10 showdistances=FALSE
ComponentClearance ComponentClearance_Vias [InComponentClass('All Components')] p10: gap=30 collisioncheckmode=3 verticalgap=10 showdistances=FALSE
DiffPairsRouting [All] p1: maxlimit=100 minlimit=10 mostfreqgap=10 toplayer_minwidth=6.3 toplayer_maxwidth=15 toplayer_prefwidth=10 midlayer1_minwidth=15 midlayer1_maxwidth=15 midlayer1_prefwidth=15 midlayer2_minwidth=15 midlayer2_maxwidth=15 midlayer2_prefwidth=15 bottomlayer_minwidth=6.3 bottomlayer_maxwidth=15 bottomlayer_prefwidth=10 maxuncoupledlength=1000
FabricationTestPointUsage TestPointUsage [All] p1: valid=2 allowmultiple=FALSE
FabricationTestpoint Testpoint [All] p1: side=3 testpointundercomponent=TRUE minsize=40 maxsize=100 preferedsize=60 minholesize=0 maxholesize=40 preferedholesize=32 testpointgrid=1 allowsidetop=TRUE allowsidebottom=TRUE usegrid=TRUE gridtolerance=0.01
FanoutControl Fanout_LCC [IsLCC] p1: bgadir=Out bgaviamode=Centered fanoutstyle=Auto fanoutdirection=Alternating viagrid=1 // Fanout_LCC (Default Rule)
FanoutControl Fanout_BGA [IsBGA] p2: bgadir=Out bgaviamode=Centered fanoutstyle=Auto fanoutdirection=Alternating viagrid=1 // Fanout_BGA (Default Rule)
FanoutControl Fanout_Default [All] p4: bgadir=Out bgaviamode=Centered fanoutstyle=Auto fanoutdirection=Alternating viagrid=1 // Fanout_Default (Default Rule)
FanoutControl Fanout_Small [(CompPinCount < 5)] p5: bgadir=Out bgaviamode=Centered fanoutstyle=Auto fanoutdirection=OutThenIn viagrid=1 // Fanout_Small (Default Rule)
HoleSize [All] p1: absolutevalues=TRUE maxlimit=251 minlimit=7.87 maxpercent=80.000 minpercent=20.000
MinimumAnnularRing MinimumAnnularRing_ThermalPadVias [IsVia and InAnyComponent] p1: minimumring=5.91
MinimumAnnularRing [All] p2: minimumring=7.87
MinimumSolderMaskSliver MinimumSolderMaskSliver_Logo [InComponentClass('Logo') vs InComponentClass('Logo')] p1: minsoldermaskwidth=0.7
MinimumSolderMaskSliver [All] p2: minsoldermaskwidth=3.94
PlaneClearance [All] p1 off: clearance=10
PlaneConnect [All] p1: planeconnectstyle=Direct reliefexpansion=10 reliefentries=4 reliefconductorwidth=10 reliefairgap=10
PolygonConnect PolygonConnect_91 [All vs IsNamedPolygon('TOP_LAYER_EZFET_USB_SHIELD_P235') Or IsNamedPolygon('TOP_LAYER_GND_P234') Or IsNamedPolygon('TOP_LAYER_GND_P243') Or IsNamedPolygon('TOP_LAYER_NETF1_2_P241') Or IsNamedPolygon('TOP_LAYER_NONET_P-001') Or IsNamedPolygon('TOP_LAYER_NONET_P-001') Or IsNamedPolygon('TOP_LAYER_OUT1_P240') Or IsNamedPolygon('TOP_LAYER_OUT2_P269') Or IsNamedPolygon('TOP_LAYER_P_IN_P238') Or IsNamedPolygon('TOP_LAYER_VBAT_P236') Or IsNamedPolygon('TOP_LAYER_VM_P233') Or IsNamedPolygon('TOP_LAYER_VM_P237') Or IsNamedPolygon('SIGNAL_LAYER_1_GND_P244') Or IsNamedPolygon('SIGNAL_LAYER_1_GND_P246') Or IsNamedPolygon('TOP_LAYER_NONET_P-001') Or IsNamedPolygon('SIGNAL_LAYER_2_3V3_MCU_P254') Or IsNamedPolygon('SIGNAL_LAYER_2_3V3_P250') Or IsNamedPolygon('SIGNAL_LAYER_2_EZFET_VBUS_P249') Or IsNamedPolygon('SIGNAL_LAYER_2_EZFET_VCC_P255') Or IsNamedPolygon('SIGNAL_LAYER_2_GND_P257') Or IsNamedPolygon('SIGNAL_LAYER_2_NETF1_2_P253') Or IsNamedPolygon('SIGNAL_LAYER_2_P_IN_P251') Or IsNamedPolygon('SIGNAL_LAYER_2_VBAT_P248') Or IsNamedPolygon('SIGNAL_LAYER_2_VM_P247') Or IsNamedPolygon('SIGNAL_LAYER_2_VM_P252') Or IsNamedPolygon('SIGNAL_LAYER_2_VM_P256') Or IsNamedPolygon('BOTTOM_LAYER_EZFET_USB_SHIELD_P258') Or IsNamedPolygon('BOTTOM_LAYER_GND_P259') Or IsNamedPolygon('BOTTOM_LAYER_GND_P267') Or IsNamedPolygon('BOTTOM_LAYER_NETF1_2_P265') Or IsNamedPolygon('BOTTOM_LAYER_P_IN_P262') Or IsNamedPolygon('BOTTOM_LAYER_VBAT_P261') Or IsNamedPolygon('BOTTOM_LAYER_VM_P266') Or IsNamedPolygon('TOP_LAYER_NONET_P-001') Or IsNamedPolygon('TOP_LAYER_NONET_P-001')] p1: connectstyle=Direct reliefconductorwidth=10 reliefentries=4 polygonreliefangle="90 Angle" airgapwidth=10
PolygonConnect [All] p2: connectstyle=Direct reliefconductorwidth=10 reliefentries=4 polygonreliefangle="90 Angle" airgapwidth=10
PolygonConnect PolygonConnect_90 [All vs IsNamedPolygon('TOP_LAYER_OUT2_P268')] p3: connectstyle=Direct reliefconductorwidth=10 reliefentries=4 polygonreliefangle="90 Angle" airgapwidth=10
PolygonConnect PolygonConnect_89 [All vs IsNamedPolygon('TOP_LAYER_OUT2_P268') Or IsNamedPolygon('TOP_LAYER_P_IN_P238') Or IsNamedPolygon('TOP_LAYER_VBAT_P236') Or IsNamedPolygon('TOP_LAYER_VM_P233') Or IsNamedPolygon('TOP_LAYER_VM_P237') Or IsNamedPolygon('SIGNAL_LAYER_1_GND_P244') Or IsNamedPolygon('SIGNAL_LAYER_1_GND_P246') Or IsNamedPolygon('TOP_LAYER_NONET_P-001') Or IsNamedPolygon('SIGNAL_LAYER_2_3V3_MCU_P254') Or IsNamedPolygon('SIGNAL_LAYER_2_3V3_P250') Or IsNamedPolygon('SIGNAL_LAYER_2_EZFET_VBUS_P249') Or IsNamedPolygon('SIGNAL_LAYER_2_EZFET_VCC_P255') Or IsNamedPolygon('SIGNAL_LAYER_2_GND_P257') Or IsNamedPolygon('SIGNAL_LAYER_2_NETF1_2_P253') Or IsNamedPolygon('SIGNAL_LAYER_2_P_IN_P251') Or IsNamedPolygon('SIGNAL_LAYER_2_VBAT_P248') Or IsNamedPolygon('SIGNAL_LAYER_2_VM_P247') Or IsNamedPolygon('SIGNAL_LAYER_2_VM_P252') Or IsNamedPolygon('SIGNAL_LAYER_2_VM_P256') Or IsNamedPolygon('BOTTOM_LAYER_EZFET_USB_SHIELD_P258') Or IsNamedPolygon('BOTTOM_LAYER_GND_P259') Or IsNamedPolygon('BOTTOM_LAYER_GND_P267') Or IsNamedPolygon('BOTTOM_LAYER_NETF1_2_P265') Or IsNamedPolygon('BOTTOM_LAYER_P_IN_P262') Or IsNamedPolygon('BOTTOM_LAYER_VBAT_P261') Or IsNamedPolygon('BOTTOM_LAYER_VM_P266') Or IsNamedPolygon('TOP_LAYER_NONET_P-001') Or IsNamedPolygon('TOP_LAYER_NONET_P-001') Or IsNamedPolygon('TOP_LAYER_NONET_P-001')] p4: connectstyle=Direct reliefconductorwidth=10 reliefentries=4 polygonreliefangle="90 Angle" airgapwidth=10
PolygonConnect PolygonConnect_88 [All vs IsNamedPolygon('TOP_LAYER_OUT2_P268')] p5: connectstyle=Direct reliefconductorwidth=10 reliefentries=4 polygonreliefangle="90 Angle" airgapwidth=10
PolygonConnect PolygonConnect_87 [All vs IsNamedPolygon('TOP_LAYER_OUT2_P268')] p6: connectstyle=Direct reliefconductorwidth=10 reliefentries=4 polygonreliefangle="90 Angle" airgapwidth=10
PolygonConnect PolygonConnect_86 [All vs IsNamedPolygon('TOP_LAYER_OUT2_P268')] p7: connectstyle=Direct reliefconductorwidth=10 reliefentries=4 polygonreliefangle="90 Angle" airgapwidth=10
PolygonConnect PolygonConnect_85 [All vs IsNamedPolygon('TOP_LAYER_EZFET_USB_SHIELD_P235')] p8: connectstyle=Direct reliefconductorwidth=10 reliefentries=4 polygonreliefangle="90 Angle" airgapwidth=10
PolygonConnect PolygonConnect_84 [All vs IsNamedPolygon('TOP_LAYER_EZFET_USB_SHIELD_P235') Or IsNamedPolygon('TOP_LAYER_GND_P234') Or IsNamedPolygon('TOP_LAYER_GND_P243') Or IsNamedPolygon('TOP_LAYER_NETF1_2_P241') Or IsNamedPolygon('TOP_LAYER_NONET_P-001') Or IsNamedPolygon('TOP_LAYER_OUT1_P240') Or IsNamedPolygon('TOP_LAYER_OUT2_P239') Or IsNamedPolygon('TOP_LAYER_P_IN_P238') Or IsNamedPolygon('TOP_LAYER_VBAT_P236') Or IsNamedPolygon('TOP_LAYER_VM_P233') Or IsNamedPolygon('TOP_LAYER_VM_P237') Or IsNamedPolygon('SIGNAL_LAYER_1_GND_P244') Or IsNamedPolygon('SIGNAL_LAYER_1_GND_P246') Or IsNamedPolygon('TOP_LAYER_NONET_P-001') Or IsNamedPolygon('SIGNAL_LAYER_2_3V3_MCU_P254') Or IsNamedPolygon('SIGNAL_LAYER_2_3V3_P250') Or IsNamedPolygon('SIGNAL_LAYER_2_EZFET_VBUS_P249') Or IsNamedPolygon('SIGNAL_LAYER_2_EZFET_VCC_P255') Or IsNamedPolygon('SIGNAL_LAYER_2_GND_P257') Or IsNamedPolygon('SIGNAL_LAYER_2_NETF1_2_P253') Or IsNamedPolygon('SIGNAL_LAYER_2_P_IN_P251') Or IsNamedPolygon('SIGNAL_LAYER_2_VBAT_P248') Or IsNamedPolygon('SIGNAL_LAYER_2_VM_P247') Or IsNamedPolygon('SIGNAL_LAYER_2_VM_P252') Or IsNamedPolygon('SIGNAL_LAYER_2_VM_P256') Or IsNamedPolygon('BOTTOM_LAYER_EZFET_USB_SHIELD_P258') Or IsNamedPolygon('BOTTOM_LAYER_GND_P259') Or IsNamedPolygon('BOTTOM_LAYER_GND_P267') Or IsNamedPolygon('BOTTOM_LAYER_NETF1_2_P265') Or IsNamedPolygon('BOTTOM_LAYER_P_IN_P262') Or IsNamedPolygon('BOTTOM_LAYER_VBAT_P261') Or IsNamedPolygon('BOTTOM_LAYER_VM_P266') Or IsNamedPolygon('TOP_LAYER_NONET_P-001') Or IsNamedPolygon('TOP_LAYER_NONET_P-001') Or IsNamedPolygon('TOP_LAYER_NONET_P-001')] p9: connectstyle=Direct reliefconductorwidth=10 reliefentries=4 polygonreliefangle="90 Angle" airgapwidth=10
PolygonConnect PolygonConnect_83 [All vs IsNamedPolygon('TOP_LAYER_EZFET_USB_SHIELD_P235')] p10: connectstyle=Direct reliefconductorwidth=10 reliefentries=4 polygonreliefangle="90 Angle" airgapwidth=10
PolygonConnect PolygonConnect_82 [All vs IsNamedPolygon('TOP_LAYER_NONET_P-001')] p11: connectstyle=Direct reliefconductorwidth=10 reliefentries=4 polygonreliefangle="90 Angle" airgapwidth=10
PolygonConnect PolygonConnect_81 [All vs IsNamedPolygon('TOP_LAYER_GND_P227')] p12: connectstyle=Direct reliefconductorwidth=10 reliefentries=4 polygonreliefangle="90 Angle" airgapwidth=10
PolygonConnect PolygonConnect_80 [All vs IsNamedPolygon('TOP_LAYER_GND_P129')] p13: connectstyle=Direct reliefconductorwidth=10 reliefentries=4 polygonreliefangle="90 Angle" airgapwidth=10
PolygonConnect PolygonConnect_79 [All vs IsNamedPolygon('TOP_LAYER_VM_P229')] p14: connectstyle=Direct reliefconductorwidth=10 reliefentries=4 polygonreliefangle="90 Angle" airgapwidth=10
PolygonConnect PolygonConnect_78 [All vs IsNamedPolygon('TOP_LAYER_GND_P129')] p15: connectstyle=Direct reliefconductorwidth=10 reliefentries=4 polygonreliefangle="90 Angle" airgapwidth=10
PolygonConnect PolygonConnect_77 [All vs IsNamedPolygon('TOP_LAYER_OUT1_P221')] p16: connectstyle=Direct reliefconductorwidth=10 reliefentries=4 polygonreliefangle="90 Angle" airgapwidth=10
PolygonConnect PolygonConnect_76 [All vs IsNamedPolygon('TOP_LAYER_OUT1_P125')] p17: connectstyle=Direct reliefconductorwidth=10 reliefentries=4 polygonreliefangle="90 Angle" airgapwidth=10
PolygonConnect PolygonConnect_75 [All vs IsNamedPolygon('TOP_LAYER_OUT1_P125')] p18: connectstyle=Direct reliefconductorwidth=10 reliefentries=4 polygonreliefangle="90 Angle" airgapwidth=10
PolygonConnect PolygonConnect_74 [All vs IsNamedPolygon('TOP_LAYER_OUT1_P125')] p19: connectstyle=Direct reliefconductorwidth=10 reliefentries=4 polygonreliefangle="90 Angle" airgapwidth=10
PolygonConnect PolygonConnect_73 [All vs IsNamedPolygon('TOP_LAYER_OUT1_P221')] p20: connectstyle=Direct reliefconductorwidth=10 reliefentries=4 polygonreliefangle="90 Angle" airgapwidth=10
PolygonConnect PolygonConnect_72 [All vs IsNamedPolygon('TOP_LAYER_GND_P121')] p21: connectstyle=Direct reliefconductorwidth=10 reliefentries=4 polygonreliefangle="90 Angle" airgapwidth=10
PolygonConnect PolygonConnect_71 [All vs IsNamedPolygon('TOP_LAYER_OUT1_P125') Or  IsNamedPolygon('TOP_LAYER_OUT2_P119')] p22: connectstyle=Direct reliefconductorwidth=10 reliefentries=4 polygonreliefangle="90 Angle" airgapwidth=10
PolygonConnect PolygonConnect_70 [All vs IsNamedPolygon('TOP_LAYER_OUT1_P125')] p23: connectstyle=Direct reliefconductorwidth=10 reliefentries=4 polygonreliefangle="90 Angle" airgapwidth=10
PolygonConnect PolygonConnect_69 [All vs IsNamedPolygon('TOP_LAYER_OUT2_P119')] p24: connectstyle=Direct reliefconductorwidth=10 reliefentries=4 polygonreliefangle="90 Angle" airgapwidth=10
PolygonConnect PolygonConnect_68 [All vs IsNamedPolygon('TOP_LAYER_VM_P085')] p25: connectstyle=Direct reliefconductorwidth=10 reliefentries=4 polygonreliefangle="90 Angle" airgapwidth=10
PolygonConnect PolygonConnect_67 [All vs IsNamedPolygon('BOTTOM_LAYER_P_IN_P174')] p26: connectstyle=Direct reliefconductorwidth=10 reliefentries=4 polygonreliefangle="90 Angle" airgapwidth=10
PolygonConnect PolygonConnect_66 [All vs IsNamedPolygon('BOTTOM_LAYER_NETF1_2_P203')] p27: connectstyle=Direct reliefconductorwidth=10 reliefentries=4 polygonreliefangle="90 Angle" airgapwidth=10
PolygonConnect PolygonConnect_65 [All vs IsNamedPolygon('BOTTOM_LAYER_VBAT_P080')] p28: connectstyle=Direct reliefconductorwidth=10 reliefentries=4 polygonreliefangle="90 Angle" airgapwidth=10
PolygonConnect PolygonConnect_64 [All vs IsNamedPolygon('TOP_LAYER_VM_P167')] p29: connectstyle=Direct reliefconductorwidth=10 reliefentries=4 polygonreliefangle="90 Angle" airgapwidth=10
PolygonConnect PolygonConnect_63 [All vs IsNamedPolygon('TOP_LAYER_VM_P167')] p30: connectstyle=Direct reliefconductorwidth=10 reliefentries=4 polygonreliefangle="90 Angle" airgapwidth=10
PolygonConnect PolygonConnect_62 [All vs IsNamedPolygon('TOP_LAYER_VM_P171')] p31: connectstyle=Direct reliefconductorwidth=10 reliefentries=4 polygonreliefangle="90 Angle" airgapwidth=10
PolygonConnect PolygonConnect_61 [All vs IsNamedPolygon('SIGNAL_LAYER_2_GND_P199')] p32: connectstyle=Direct reliefconductorwidth=10 reliefentries=4 polygonreliefangle="90 Angle" airgapwidth=10
PolygonConnect PolygonConnect_60 [All vs IsNamedPolygon('SIGNAL_LAYER_2_NETF1_2_P196')] p33: connectstyle=Direct reliefconductorwidth=10 reliefentries=4 polygonreliefangle="90 Angle" airgapwidth=10
PolygonConnect PolygonConnect_59 [All vs IsNamedPolygon('SIGNAL_LAYER_2_VBAT_P197')] p34: connectstyle=Direct reliefconductorwidth=10 reliefentries=4 polygonreliefangle="90 Angle" airgapwidth=10
PolygonConnect PolygonConnect_58 [All vs IsNamedPolygon('SIGNAL_LAYER_2_P_IN_P198')] p35: connectstyle=Direct reliefconductorwidth=10 reliefentries=4 polygonreliefangle="90 Angle" airgapwidth=10
PolygonConnect PolygonConnect_57 [All vs IsNamedPolygon('SIGNAL_LAYER_2_3V3_P194')] p36: connectstyle=Direct reliefconductorwidth=10 reliefentries=4 polygonreliefangle="90 Angle" airgapwidth=10
PolygonConnect PolygonConnect_56 [All vs IsNamedPolygon('TOP_LAYER_NETF1_2_P201')] p37: connectstyle=Direct reliefconductorwidth=10 reliefentries=4 polygonreliefangle="90 Angle" airgapwidth=10
PolygonConnect PolygonConnect_55 [All vs IsNamedPolygon('TOP_LAYER_VBAT_P207')] p38: connectstyle=Direct reliefconductorwidth=10 reliefentries=4 polygonreliefangle="90 Angle" airgapwidth=10
PolygonConnect PolygonConnect_54 [All vs IsNamedPolygon('TOP_LAYER_P_IN_P223')] p39: connectstyle=Direct reliefconductorwidth=10 reliefentries=4 polygonreliefangle="90 Angle" airgapwidth=10
PolygonConnect PolygonConnect_53 [All vs IsNamedPolygon('TOP_LAYER_GND_P129')] p40: connectstyle=Direct reliefconductorwidth=10 reliefentries=4 polygonreliefangle="90 Angle" airgapwidth=10
PolygonConnect PolygonConnect_52 [All vs IsNamedPolygon('SIGNAL_LAYER_2_VM_P177') Or  IsNamedPolygon('SIGNAL_LAYER_2_VM_P179') Or  IsNamedPolygon('SIGNAL_LAYER_2_VM_P160') Or  IsNamedPolygon('SIGNAL_LAYER_2_VM_P175') Or  IsNamedPolygon('SIGNAL_LAYER_2_VM_P181')] p41: connectstyle=Direct reliefconductorwidth=10 reliefentries=4 polygonreliefangle="90 Angle" airgapwidth=10
PolygonConnect PolygonConnect_51 [All vs IsNamedPolygon('SIGNAL_LAYER_2_EZFET_VBUS_P136')] p42: connectstyle=Direct reliefconductorwidth=10 reliefentries=4 polygonreliefangle="90 Angle" airgapwidth=10
PolygonConnect PolygonConnect_50 [All vs IsNamedPolygon('SIGNAL_LAYER_2_EZFET_VCC_P132')] p43: connectstyle=Direct reliefconductorwidth=10 reliefentries=4 polygonreliefangle="90 Angle" airgapwidth=10
PolygonConnect PolygonConnect_49 [All vs IsNamedPolygon('SIGNAL_LAYER_2_3V3_MCU_P192')] p44: connectstyle=Direct reliefconductorwidth=10 reliefentries=4 polygonreliefangle="90 Angle" airgapwidth=10
PolygonConnect PolygonConnect_48 [All vs IsNamedPolygon('SIGNAL_LAYER_1_GND_P190')] p45: connectstyle=Direct reliefconductorwidth=10 reliefentries=4 polygonreliefangle="90 Angle" airgapwidth=10
PolygonConnect PolygonConnect_47 [All vs IsNamedPolygon('SIGNAL_LAYER_1_GND_P184')] p46: connectstyle=Direct reliefconductorwidth=10 reliefentries=4 polygonreliefangle="90 Angle" airgapwidth=10
PolygonConnect PolygonConnect_46 [All vs IsNamedPolygon('BOTTOM_LAYER_GND_P231')] p47: connectstyle=Direct reliefconductorwidth=10 reliefentries=4 polygonreliefangle="90 Angle" airgapwidth=10
PolygonConnect PolygonConnect_45 [All vs IsNamedPolygon('BOTTOM_LAYER_GND_P231')] p48: connectstyle=Direct reliefconductorwidth=10 reliefentries=4 polygonreliefangle="90 Angle" airgapwidth=10
PolygonConnect PolygonConnect_44 [All vs IsNamedPolygon('BOTTOM_LAYER_OUT2_P163')] p49: connectstyle=Direct reliefconductorwidth=10 reliefentries=4 polygonreliefangle="90 Angle" airgapwidth=10
PolygonConnect PolygonConnect_43 [All vs IsNamedPolygon('BOTTOM_LAYER_VM_P166')] p50: connectstyle=Direct reliefconductorwidth=10 reliefentries=4 polygonreliefangle="90 Angle" airgapwidth=10
PolygonConnect PolygonConnect_42 [All vs IsNamedPolygon('BOTTOM_LAYER_VM_P219')] p51: connectstyle=Direct reliefconductorwidth=10 reliefentries=4 polygonreliefangle="90 Angle" airgapwidth=10
PolygonConnect PolygonConnect_41 [All vs IsNamedPolygon('BOTTOM_LAYER_OUT1_P164')] p52: connectstyle=Direct reliefconductorwidth=10 reliefentries=4 polygonreliefangle="90 Angle" airgapwidth=10
PolygonConnect PolygonConnect_40 [All vs IsNamedPolygon('BOTTOM_LAYER_GND_P162')] p53: connectstyle=Direct reliefconductorwidth=10 reliefentries=4 polygonreliefangle="90 Angle" airgapwidth=10
PolygonConnect PolygonConnect_39 [All vs IsNamedPolygon('SIGNAL_LAYER_2_VM_P160')] p54: connectstyle=Direct reliefconductorwidth=10 reliefentries=4 polygonreliefangle="90 Angle" airgapwidth=10
PolygonConnect PolygonConnect_38 [All vs IsNamedPolygon('SIGNAL_LAYER_2_NONET_P138')] p55: connectstyle=Direct reliefconductorwidth=10 reliefentries=4 polygonreliefangle="90 Angle" airgapwidth=10
PolygonConnect PolygonConnect_37 [All vs IsNamedPolygon('SIGNAL_LAYER_1_VM_P146')] p56: connectstyle=Direct reliefconductorwidth=10 reliefentries=4 polygonreliefangle="90 Angle" airgapwidth=10
PolygonConnect PolygonConnect_36 [All vs IsNamedPolygon('SIGNAL_LAYER_2_GND_P156')] p57: connectstyle=Direct reliefconductorwidth=10 reliefentries=4 polygonreliefangle="90 Angle" airgapwidth=10
PolygonConnect PolygonConnect_35 [All vs IsNamedPolygon('BOTTOM_LAYER_EZFET_USB_SHIELD_P211')] p58: connectstyle=Direct reliefconductorwidth=10 reliefentries=4 polygonreliefangle="90 Angle" airgapwidth=10
PolygonConnect PolygonConnect_34 [All vs IsNamedPolygon('SIGNAL_LAYER_1_VM_P144')] p59: connectstyle=Direct reliefconductorwidth=10 reliefentries=4 polygonreliefangle="90 Angle" airgapwidth=10
PolygonConnect PolygonConnect_33 [All vs IsNamedPolygon('SIGNAL_LAYER_1_VM_P148') Or  IsNamedPolygon('SIGNAL_LAYER_1_VM_P148')] p60: connectstyle=Direct reliefconductorwidth=10 reliefentries=4 polygonreliefangle="90 Angle" airgapwidth=10
PolygonConnect PolygonConnect_32 [All vs IsNamedPolygon('SIGNAL_LAYER_1_GND_P154')] p61: connectstyle=Direct reliefconductorwidth=10 reliefentries=4 polygonreliefangle="90 Angle" airgapwidth=10
PolygonConnect PolygonConnect_31 [All vs IsNamedPolygon('SIGNAL_LAYER_2_NONET_P138')] p62: connectstyle=Direct reliefconductorwidth=10 reliefentries=4 polygonreliefangle="90 Angle" airgapwidth=10
PolygonConnect PolygonConnect_30 [All vs IsNamedPolygon('SIGNAL_LAYER_2_GND_P082')] p63: connectstyle=Direct reliefconductorwidth=10 reliefentries=4 polygonreliefangle="90 Angle" airgapwidth=10
PolygonConnect PolygonConnect_29 [All vs IsNamedPolygon('TOP_LAYER_GND_P076')] p64: connectstyle=Direct reliefconductorwidth=10 reliefentries=4 polygonreliefangle="90 Angle" airgapwidth=10
PolygonConnect PolygonConnect_28 [All vs IsNamedPolygon('TOP_LAYER_GND_P087')] p65: connectstyle=Direct reliefconductorwidth=10 reliefentries=4 polygonreliefangle="90 Angle" airgapwidth=10
PolygonConnect PolygonConnect_27 [All vs IsNamedPolygon('TOP_LAYER_VM_P127') Or  IsNamedPolygon('TOP_LAYER_VM_P085')] p66: connectstyle=Direct reliefconductorwidth=10 reliefentries=4 polygonreliefangle="90 Angle" airgapwidth=10
PolygonConnect PolygonConnect_26 [All vs IsNamedPolygon('TOP_LAYER_GND_P117')] p67: connectstyle=Direct reliefconductorwidth=10 reliefentries=4 polygonreliefangle="90 Angle" airgapwidth=10
PolygonConnect PolygonConnect_25 [All vs IsNamedPolygon('TOP_LAYER_OUT2_P119') Or  IsNamedPolygon('TOP_LAYER_OUT1_P125')] p68: connectstyle=Direct reliefconductorwidth=10 reliefentries=4 polygonreliefangle="90 Angle" airgapwidth=10
PolygonConnect PolygonConnect_24 [All vs IsNamedPolygon('SIGNAL_LAYER_2_NONET_P113')] p69: connectstyle=Direct reliefconductorwidth=10 reliefentries=4 polygonreliefangle="90 Angle" airgapwidth=10
PolygonConnect PolygonConnect_23 [All vs IsNamedPolygon('BOTTOM_LAYER_NONET_P115')] p70: connectstyle=Direct reliefconductorwidth=10 reliefentries=4 polygonreliefangle="90 Angle" airgapwidth=10
PolygonConnect PolygonConnect_22 [All vs IsNamedPolygon('SIGNAL_LAYER_1_NONET_P111')] p71: connectstyle=Direct reliefconductorwidth=10 reliefentries=4 polygonreliefangle="90 Angle" airgapwidth=10
PolygonConnect PolygonConnect_21 [All vs IsNamedPolygon('TOP_LAYER_NONET_P083')] p72: connectstyle=Direct reliefconductorwidth=10 reliefentries=4 polygonreliefangle="90 Angle" airgapwidth=10
PolygonConnect PolygonConnect_20 [All vs IsNamedPolygon('TOP_LAYER_NONET_P105')] p73: connectstyle=Direct reliefconductorwidth=10 reliefentries=4 polygonreliefangle="90 Angle" airgapwidth=10
PolygonConnect PolygonConnect_19 [All vs IsNamedPolygon('TOP_LAYER_OUT2_P107')] p74: connectstyle=Direct reliefconductorwidth=10 reliefentries=4 polygonreliefangle="90 Angle" airgapwidth=10
PolygonConnect PolygonConnect_18 [All vs IsNamedPolygon('TOP_LAYER_NONET_P101')] p75: connectstyle=Direct reliefconductorwidth=10 reliefentries=4 polygonreliefangle="90 Angle" airgapwidth=10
